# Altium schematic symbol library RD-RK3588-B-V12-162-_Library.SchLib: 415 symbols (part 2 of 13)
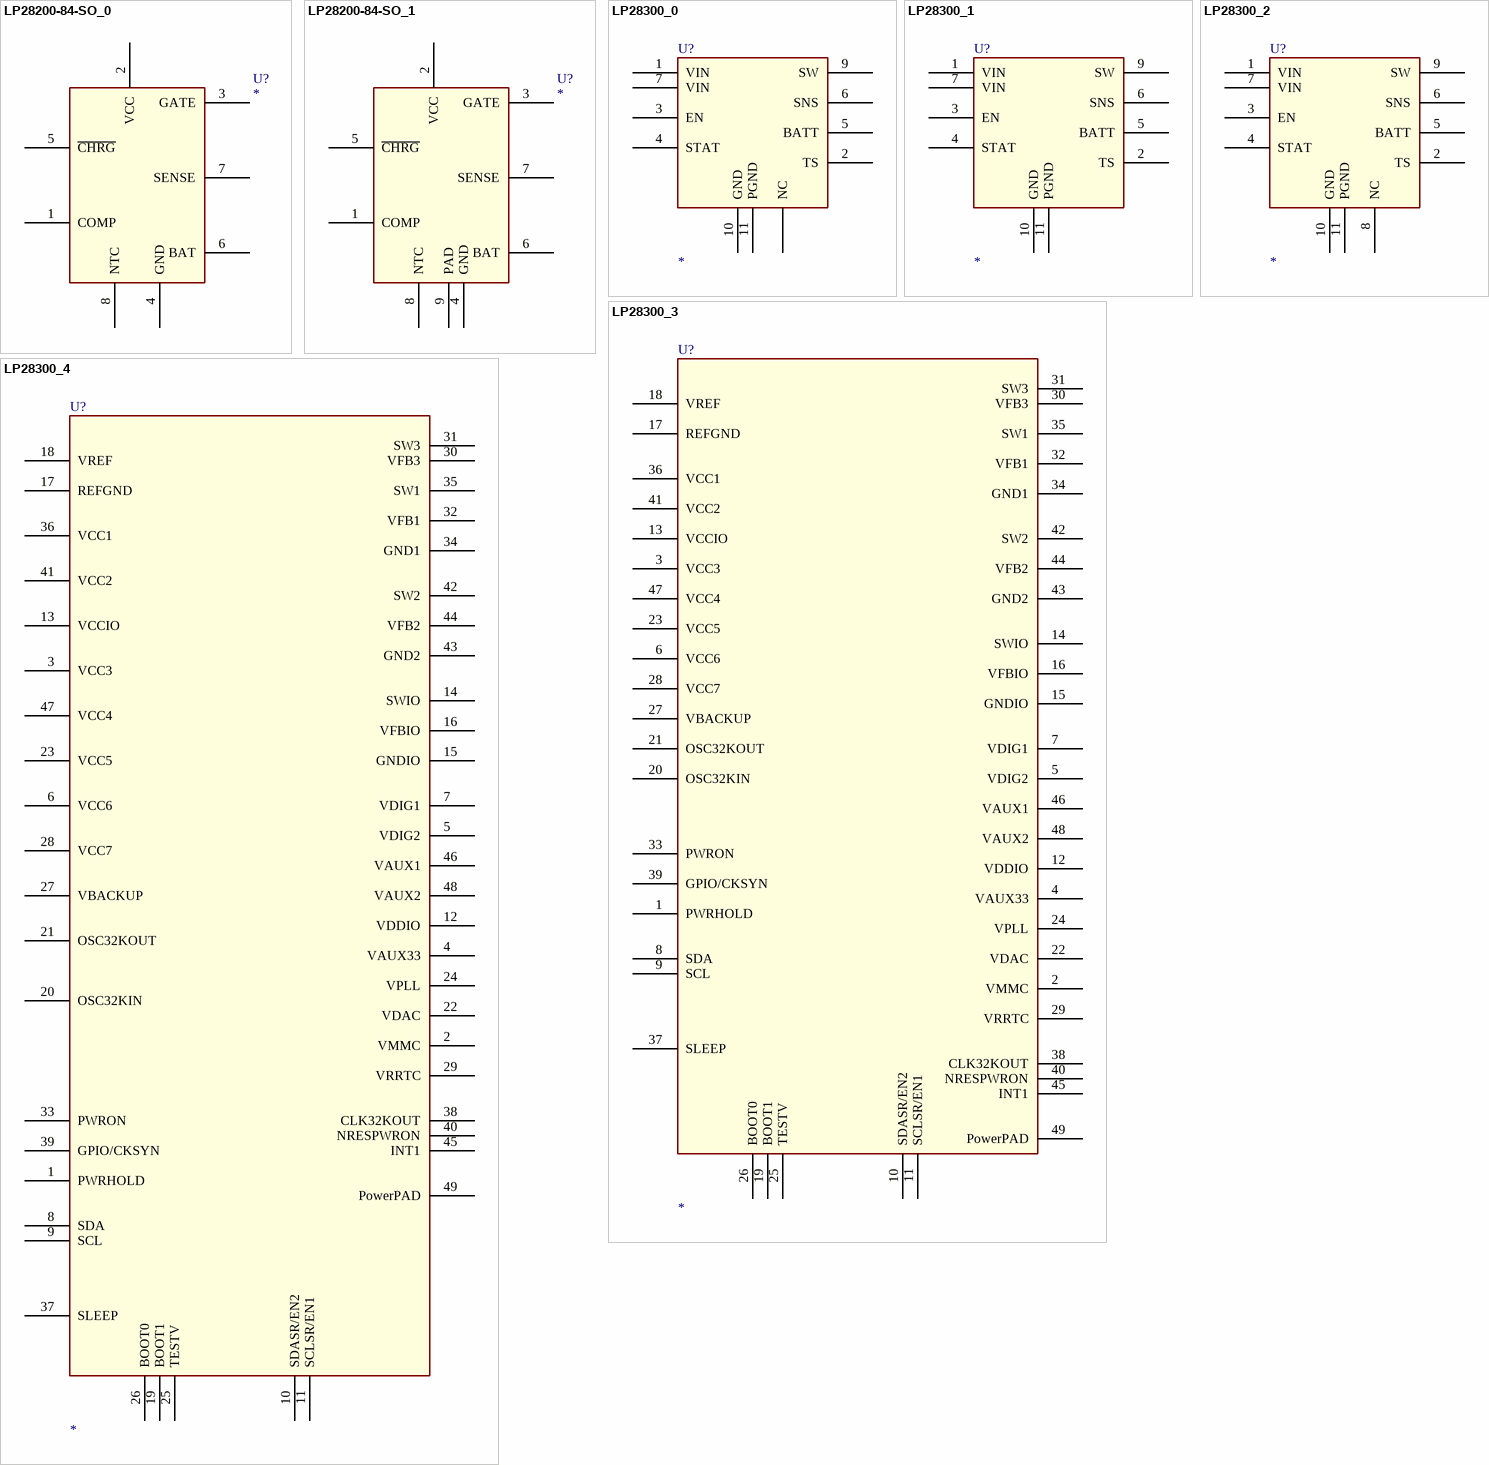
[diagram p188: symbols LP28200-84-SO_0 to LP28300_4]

## LP28300_3
designator U?
footprint TDFN10
pins: 1 PWRHOLD, 2 VMMC, 3 VCC3, 4 VAUX33, 5 VDIG2, 6 VCC6, 7 VDIG1, 8 SDA, 9 SCL, 10 SDASR/EN2, 11 SCLSR/EN1, 12 VDDIO, 13 VCCIO, 14 SWIO, 15 GNDIO, 16 VFBIO, 17 REFGND, 18 VREF, 19 BOOT1, 20 OSC32KIN, 21 OSC32KOUT, 22 VDAC, 23 VCC5, 24 VPLL, 25 TESTV, 26 BOOT0, 27 VBACKUP, 28 VCC7, 29 VRRTC, 30 VFB3, 31 SW3, 32 VFB1, 33 PWRON, 34 GND1, 35 SW1, 36 VCC1, 37 SLEEP, 38 CLK32KOUT, 39 GPIO/CKSYN, 40 NRESPWRON, 41 VCC2, 42 SW2, 43 GND2, 44 VFB2, 45 INT1, 46 VAUX1, 47 VCC4, 48 VAUX2, 49 PowerPAD

## LP28300_4
designator U?
footprint TDFN10
pins: 1 PWRHOLD, 2 VMMC, 3 VCC3, 4 VAUX33, 5 VDIG2, 6 VCC6, 7 VDIG1, 8 SDA, 9 SCL, 10 SDASR/EN2, 11 SCLSR/EN1, 12 VDDIO, 13 VCCIO, 14 SWIO, 15 GNDIO, 16 VFBIO, 17 REFGND, 18 VREF, 19 BOOT1, 20 OSC32KIN, 21 OSC32KOUT, 22 VDAC, 23 VCC5, 24 VPLL, 25 TESTV, 26 BOOT0, 27 VBACKUP, 28 VCC7, 29 VRRTC, 30 VFB3, 31 SW3, 32 VFB1, 33 PWRON, 34 GND1, 35 SW1, 36 VCC1, 37 SLEEP, 38 CLK32KOUT, 39 GPIO/CKSYN, 40 NRESPWRON, 41 VCC2, 42 SW2, 43 GND2, 44 VFB2, 45 INT1, 46 VAUX1, 47 VCC4, 48 VAUX2, 49 PowerPAD

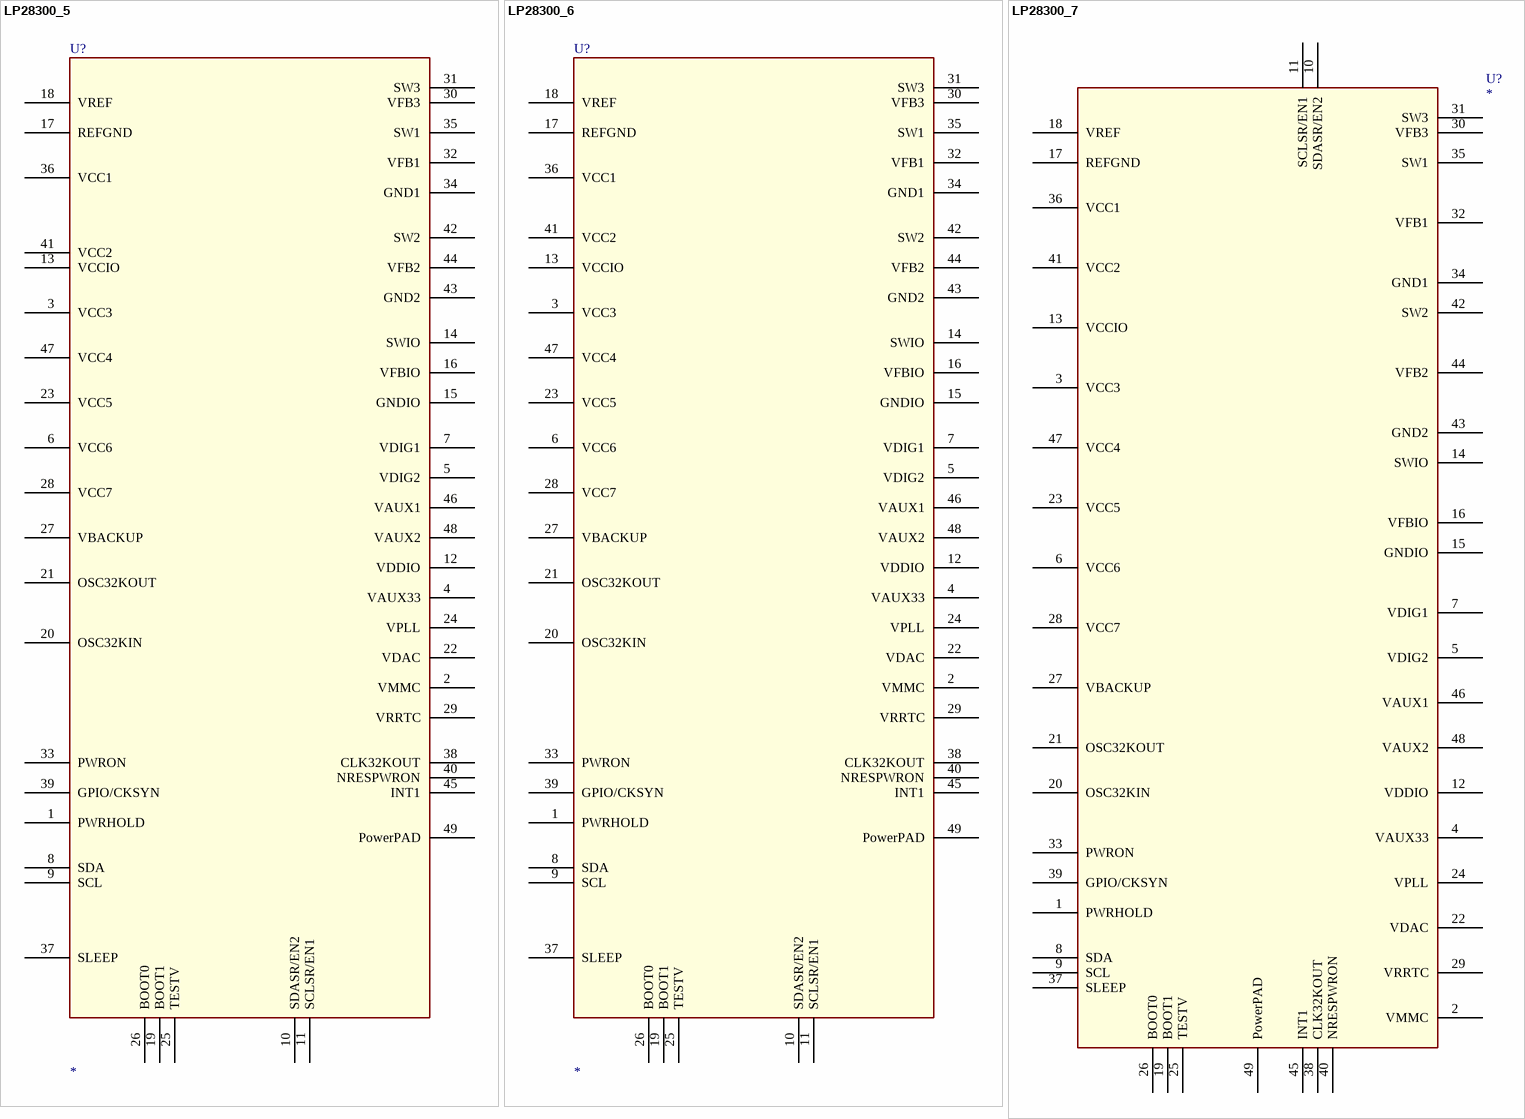
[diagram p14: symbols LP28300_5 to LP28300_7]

## LP28300_5
designator U?
footprint TDFN10
pins: 1 PWRHOLD, 2 VMMC, 3 VCC3, 4 VAUX33, 5 VDIG2, 6 VCC6, 7 VDIG1, 8 SDA, 9 SCL, 10 SDASR/EN2, 11 SCLSR/EN1, 12 VDDIO, 13 VCCIO, 14 SWIO, 15 GNDIO, 16 VFBIO, 17 REFGND, 18 VREF, 19 BOOT1, 20 OSC32KIN, 21 OSC32KOUT, 22 VDAC, 23 VCC5, 24 VPLL, 25 TESTV, 26 BOOT0, 27 VBACKUP, 28 VCC7, 29 VRRTC, 30 VFB3, 31 SW3, 32 VFB1, 33 PWRON, 34 GND1, 35 SW1, 36 VCC1, 37 SLEEP, 38 CLK32KOUT, 39 GPIO/CKSYN, 40 NRESPWRON, 41 VCC2, 42 SW2, 43 GND2, 44 VFB2, 45 INT1, 46 VAUX1, 47 VCC4, 48 VAUX2, 49 PowerPAD

## LP28300_6
designator U?
footprint TDFN10
pins: 1 PWRHOLD, 2 VMMC, 3 VCC3, 4 VAUX33, 5 VDIG2, 6 VCC6, 7 VDIG1, 8 SDA, 9 SCL, 10 SDASR/EN2, 11 SCLSR/EN1, 12 VDDIO, 13 VCCIO, 14 SWIO, 15 GNDIO, 16 VFBIO, 17 REFGND, 18 VREF, 19 BOOT1, 20 OSC32KIN, 21 OSC32KOUT, 22 VDAC, 23 VCC5, 24 VPLL, 25 TESTV, 26 BOOT0, 27 VBACKUP, 28 VCC7, 29 VRRTC, 30 VFB3, 31 SW3, 32 VFB1, 33 PWRON, 34 GND1, 35 SW1, 36 VCC1, 37 SLEEP, 38 CLK32KOUT, 39 GPIO/CKSYN, 40 NRESPWRON, 41 VCC2, 42 SW2, 43 GND2, 44 VFB2, 45 INT1, 46 VAUX1, 47 VCC4, 48 VAUX2, 49 PowerPAD

## LP28300_7
designator U?
footprint TDFN10
pins: 1 PWRHOLD, 2 VMMC, 3 VCC3, 4 VAUX33, 5 VDIG2, 6 VCC6, 7 VDIG1, 8 SDA, 9 SCL, 10 SDASR/EN2, 11 SCLSR/EN1, 12 VDDIO, 13 VCCIO, 14 SWIO, 15 GNDIO, 16 VFBIO, 17 REFGND, 18 VREF, 19 BOOT1, 20 OSC32KIN, 21 OSC32KOUT, 22 VDAC, 23 VCC5, 24 VPLL, 25 TESTV, 26 BOOT0, 27 VBACKUP, 28 VCC7, 29 VRRTC, 30 VFB3, 31 SW3, 32 VFB1, 33 PWRON, 34 GND1, 35 SW1, 36 VCC1, 37 SLEEP, 38 CLK32KOUT, 39 GPIO/CKSYN, 40 NRESPWRON, 41 VCC2, 42 SW2, 43 GND2, 44 VFB2, 45 INT1, 46 VAUX1, 47 VCC4, 48 VAUX2, 49 PowerPAD

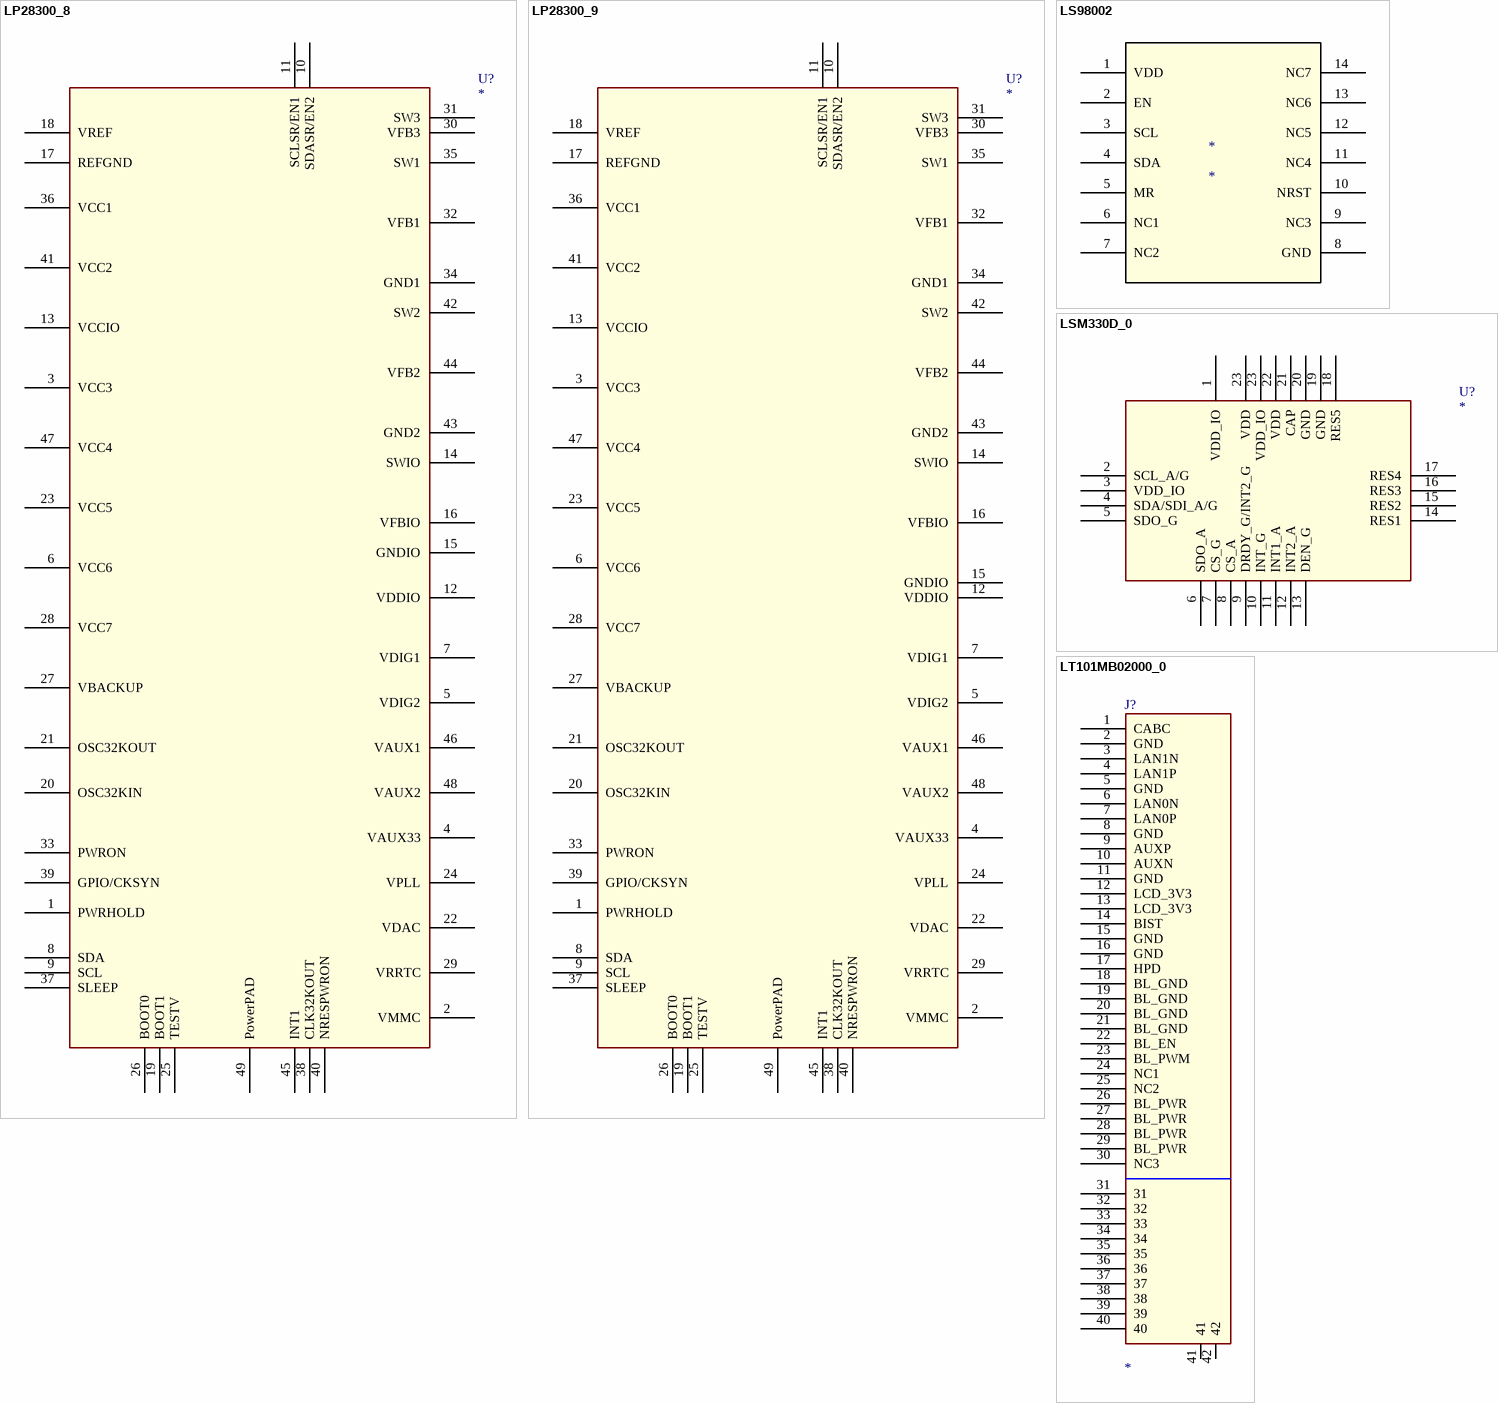
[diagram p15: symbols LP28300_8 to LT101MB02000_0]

## LP28300_8
designator U?
footprint TDFN10
pins: 1 PWRHOLD, 2 VMMC, 3 VCC3, 4 VAUX33, 5 VDIG2, 6 VCC6, 7 VDIG1, 8 SDA, 9 SCL, 10 SDASR/EN2, 11 SCLSR/EN1, 12 VDDIO, 13 VCCIO, 14 SWIO, 15 GNDIO, 16 VFBIO, 17 REFGND, 18 VREF, 19 BOOT1, 20 OSC32KIN, 21 OSC32KOUT, 22 VDAC, 23 VCC5, 24 VPLL, 25 TESTV, 26 BOOT0, 27 VBACKUP, 28 VCC7, 29 VRRTC, 30 VFB3, 31 SW3, 32 VFB1, 33 PWRON, 34 GND1, 35 SW1, 36 VCC1, 37 SLEEP, 38 CLK32KOUT, 39 GPIO/CKSYN, 40 NRESPWRON, 41 VCC2, 42 SW2, 43 GND2, 44 VFB2, 45 INT1, 46 VAUX1, 47 VCC4, 48 VAUX2, 49 PowerPAD

## LP28300_9
designator U?
footprint TDFN10
pins: 1 PWRHOLD, 2 VMMC, 3 VCC3, 4 VAUX33, 5 VDIG2, 6 VCC6, 7 VDIG1, 8 SDA, 9 SCL, 10 SDASR/EN2, 11 SCLSR/EN1, 12 VDDIO, 13 VCCIO, 14 SWIO, 15 GNDIO, 16 VFBIO, 17 REFGND, 18 VREF, 19 BOOT1, 20 OSC32KIN, 21 OSC32KOUT, 22 VDAC, 23 VCC5, 24 VPLL, 25 TESTV, 26 BOOT0, 27 VBACKUP, 28 VCC7, 29 VRRTC, 30 VFB3, 31 SW3, 32 VFB1, 33 PWRON, 34 GND1, 35 SW1, 36 VCC1, 37 SLEEP, 38 CLK32KOUT, 39 GPIO/CKSYN, 40 NRESPWRON, 41 VCC2, 42 SW2, 43 GND2, 44 VFB2, 45 INT1, 46 VAUX1, 47 VCC4, 48 VAUX2, 49 PowerPAD

## LS98002
designator *
pins: 1 VDD, 2 EN, 3 SCL, 4 SDA, 5 MR, 6 NC1, 7 NC2, 8 GND, 9 NC3, 10 NRST, 11 NC4, 12 NC5, 13 NC6, 14 NC7

## LSM330D_0
designator U?
footprint L3G4200D
pins: 1 VDD_IO, 2 SCL_A/G, 3 VDD_IO, 4 SDA/SDI_A/G, 5 SDO_G, 6 SDO_A, 7 CS_G, 8 CS_A, 9 DRDY_G/INT2_G, 10 INT_G, 11 INT1_A, 12 INT2_A, 13 DEN_G, 14 RES1, 15 RES2, 16 RES3, 17 RES4, 18 RES5, 19 GND (power), 20 GND (power), 21 CAP, 22 VDD, 23 VDD, 23 VDD_IO

## LT101MB02000_0
designator J?
pins: 1 CABC, 2 GND (power), 3 LAN1N, 4 LAN1P, 5 GND (power), 6 LAN0N, 7 LAN0P, 8 GND (power), 9 AUXP, 10 AUXN, 11 GND (power), 12 LCD_3V3 (power), 13 LCD_3V3 (power), 14 BIST, 15 GND (power), 16 GND (power), 17 HPD, 18 BL_GND (power), 19 BL_GND (power), 20 BL_GND (power), 21 BL_GND (power), 22 BL_EN, 23 BL_PWM, 24 NC1, 25 NC2, 26 BL_PWR (power), 27 BL_PWR (power), 28 BL_PWR (power), 29 BL_PWR (power), 30 NC3, 31, 32, 33, 34, 35, 36, 37, 38, 39, 40, 41, 42

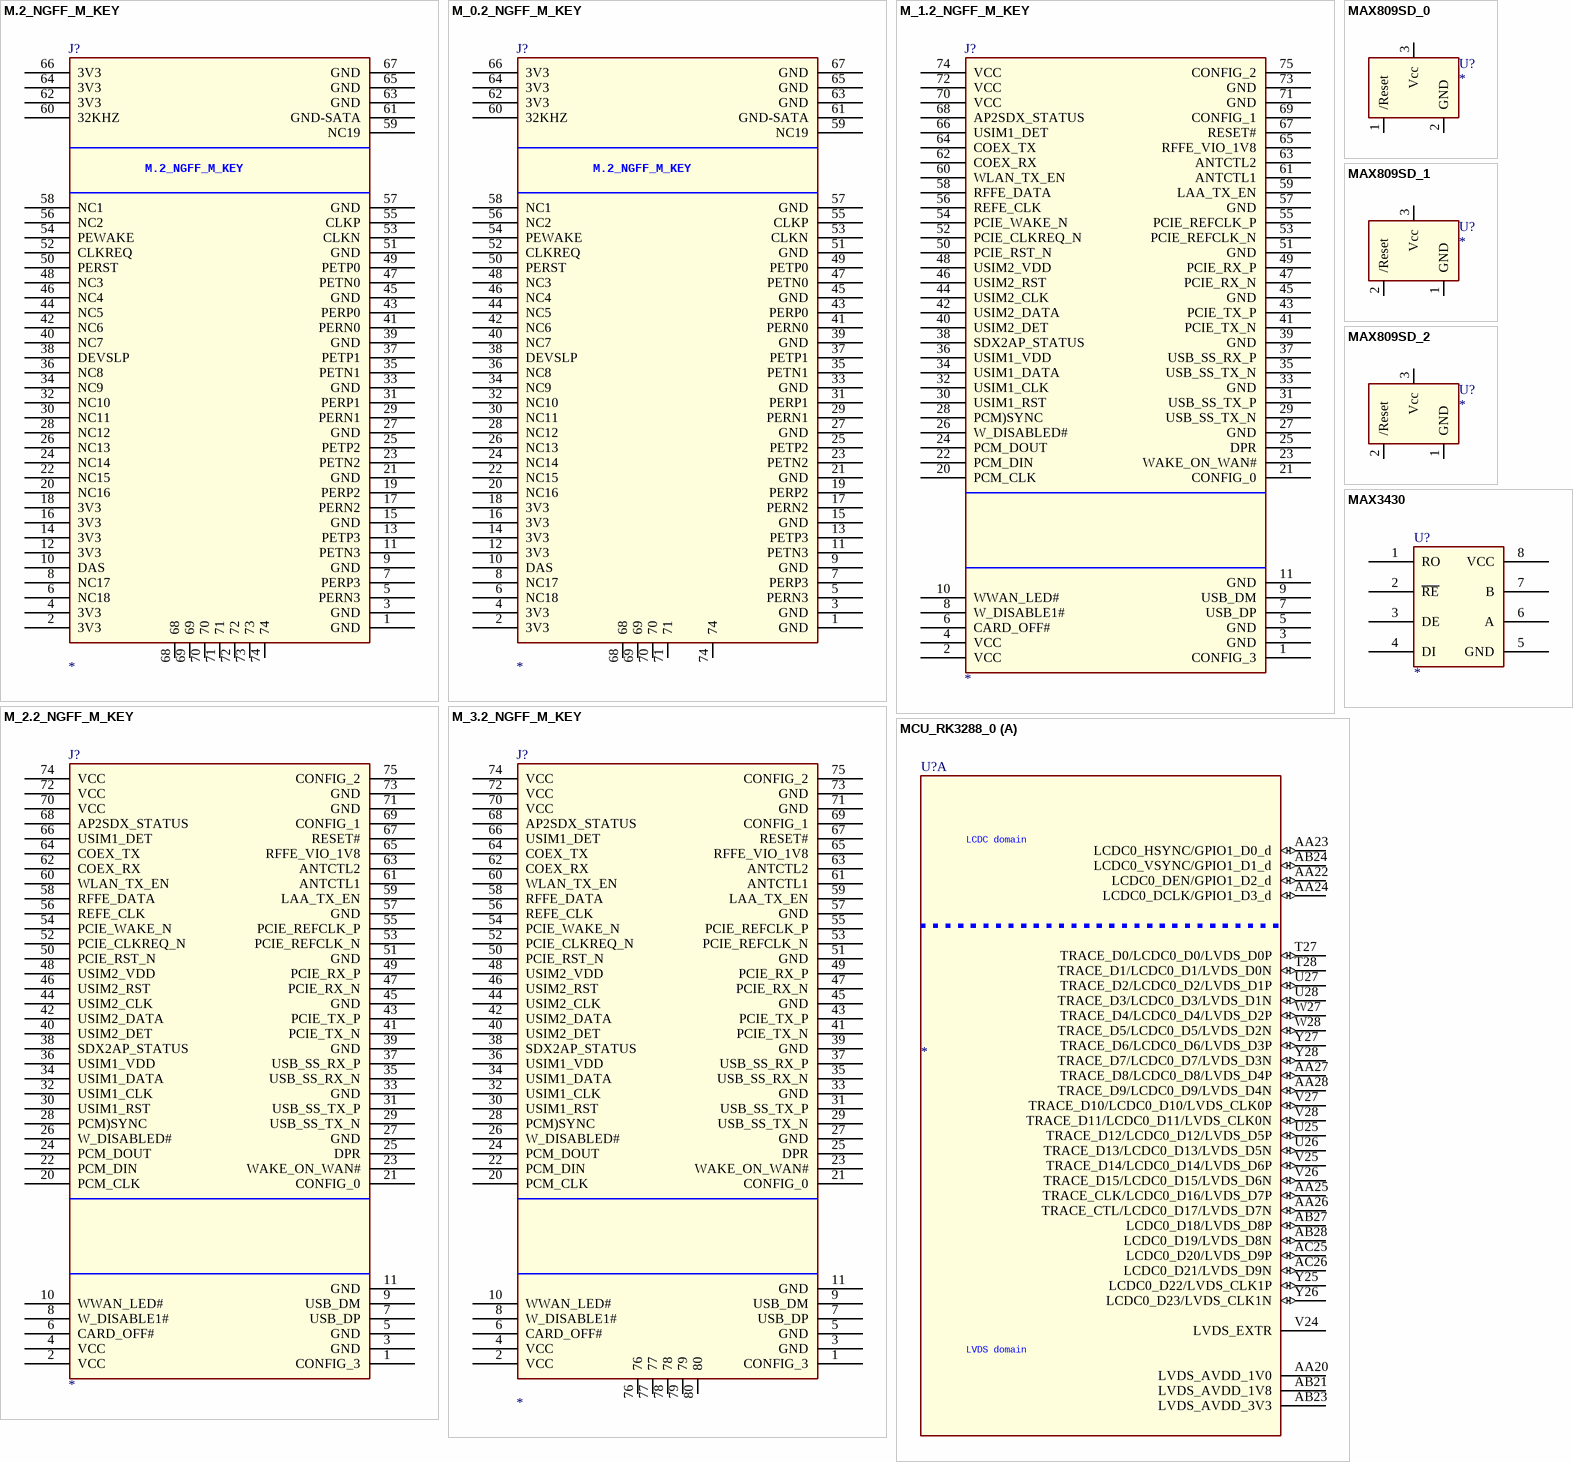
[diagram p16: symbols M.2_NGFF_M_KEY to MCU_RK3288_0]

## M.2_NGFF_M_KEY
designator J?
pins: 1 GND (power), 2 3V3 (power), 3 GND (power), 4 3V3 (power), 5 PERN3, 6 NC18, 7 PERP3, 8 NC17, 9 GND (power), 10 DAS, 11 PETN3, 12 3V3 (power), 13 PETP3, 14 3V3 (power), 15 GND (power), 16 3V3 (power), 17 PERN2, 18 3V3 (power), 19 PERP2, 20 NC16, 21 GND (power), 22 NC15, 23 PETN2, 24 NC14, 25 PETP2, 26 NC13, 27 GND (power), 28 NC12, 29 PERN1, 30 NC11, 31 PERP1, 32 NC10, 33 GND (power), 34 NC9, 35 PETN1, 36 NC8, 37 PETP1, 38 DEVSLP, 39 GND (power), 40 NC7, 41 PERN0, 42 NC6, 43 PERP0, 44 NC5, 45 GND (power), 46 NC4, 47 PETN0, 48 NC3, 49 PETP0, 50 PERST, 51 GND (power), 52 CLKREQ, 53 CLKN, 54 PEWAKE, 55 CLKP, 56 NC2, 57 GND (power), 58 NC1, 59 NC19, 60 32KHZ, 61 GND-SATA, 62 3V3 (power), 63 GND (power), 64 3V3 (power), 65 GND (power), 66 3V3 (power), 67 GND (power), 68, 69, 70, 71, 72, 73, 74

## M_0.2_NGFF_M_KEY
designator J?
pins: 1 GND (power), 2 3V3 (power), 3 GND (power), 4 3V3 (power), 5 PERN3, 6 NC18, 7 PERP3, 8 NC17, 9 GND (power), 10 DAS, 11 PETN3, 12 3V3 (power), 13 PETP3, 14 3V3 (power), 15 GND (power), 16 3V3 (power), 17 PERN2, 18 3V3 (power), 19 PERP2, 20 NC16, 21 GND (power), 22 NC15, 23 PETN2, 24 NC14, 25 PETP2, 26 NC13, 27 GND (power), 28 NC12, 29 PERN1, 30 NC11, 31 PERP1, 32 NC10, 33 GND (power), 34 NC9, 35 PETN1, 36 NC8, 37 PETP1, 38 DEVSLP, 39 GND (power), 40 NC7, 41 PERN0, 42 NC6, 43 PERP0, 44 NC5, 45 GND (power), 46 NC4, 47 PETN0, 48 NC3, 49 PETP0, 50 PERST, 51 GND (power), 52 CLKREQ, 53 CLKN, 54 PEWAKE, 55 CLKP, 56 NC2, 57 GND (power), 58 NC1, 59 NC19, 60 32KHZ, 61 GND-SATA, 62 3V3 (power), 63 GND (power), 64 3V3 (power), 65 GND (power), 66 3V3 (power), 67 GND (power), 68, 69, 70, 71, 74

## M_1.2_NGFF_M_KEY
designator J?
pins: 1 CONFIG_3, 2 VCC, 3 GND, 4 VCC, 5 GND, 6 CARD_OFF#, 7 USB_DP, 8 W_DISABLE1#, 9 USB_DM, 10 WWAN_LED#, 11 GND, 20 PCM_CLK, 21 CONFIG_0, 22 PCM_DIN, 23 WAKE_ON_WAN#, 24 PCM_DOUT, 25 DPR, 26 W_DISABLED#, 27 GND, 28 PCM)SYNC, 29 USB_SS_TX_N, 30 USIM1_RST, 31 USB_SS_TX_P, 32 USIM1_CLK, 33 GND, 34 USIM1_DATA, 35 USB_SS_TX_N, 36 USIM1_VDD, 37 USB_SS_RX_P, 38 SDX2AP_STATUS, 39 GND, 40 USIM2_DET, 41 PCIE_TX_N, 42 USIM2_DATA, 43 PCIE_TX_P, 44 USIM2_CLK, 45 GND, 46 USIM2_RST, 47 PCIE_RX_N, 48 USIM2_VDD, 49 PCIE_RX_P, 50 PCIE_RST_N, 51 GND, 52 PCIE_CLKREQ_N, 53 PCIE_REFCLK_N, 54 PCIE_WAKE_N, 55 PCIE_REFCLK_P, 56 REFE_CLK, 57 GND, 58 RFFE_DATA, 59 LAA_TX_EN, 60 WLAN_TX_EN, 61 ANTCTL1, 62 COEX_RX, 63 ANTCTL2, 64 COEX_TX, 65 RFFE_VIO_1V8, 66 USIM1_DET, 67 RESET#, 68 AP2SDX_STATUS, 69 CONFIG_1, 70 VCC, 71 GND, 72 VCC, 73 GND, 74 VCC, 75 CONFIG_2

## M_2.2_NGFF_M_KEY
designator J?
pins: 1 CONFIG_3, 2 VCC (power), 3 GND (power), 4 VCC (power), 5 GND (power), 6 CARD_OFF#, 7 USB_DP, 8 W_DISABLE1#, 9 USB_DM, 10 WWAN_LED#, 11 GND (power), 20 PCM_CLK, 21 CONFIG_0, 22 PCM_DIN, 23 WAKE_ON_WAN#, 24 PCM_DOUT, 25 DPR, 26 W_DISABLED#, 27 GND (power), 28 PCM)SYNC, 29 USB_SS_TX_N, 30 USIM1_RST, 31 USB_SS_TX_P, 32 USIM1_CLK, 33 GND (power), 34 USIM1_DATA, 35 USB_SS_RX_N, 36 USIM1_VDD, 37 USB_SS_RX_P, 38 SDX2AP_STATUS, 39 GND (power), 40 USIM2_DET, 41 PCIE_TX_N, 42 USIM2_DATA, 43 PCIE_TX_P, 44 USIM2_CLK, 45 GND (power), 46 USIM2_RST, 47 PCIE_RX_N, 48 USIM2_VDD, 49 PCIE_RX_P, 50 PCIE_RST_N, 51 GND (power), 52 PCIE_CLKREQ_N, 53 PCIE_REFCLK_N, 54 PCIE_WAKE_N, 55 PCIE_REFCLK_P, 56 REFE_CLK, 57 GND (power), 58 RFFE_DATA, 59 LAA_TX_EN, 60 WLAN_TX_EN, 61 ANTCTL1, 62 COEX_RX, 63 ANTCTL2, 64 COEX_TX, 65 RFFE_VIO_1V8, 66 USIM1_DET, 67 RESET#, 68 AP2SDX_STATUS, 69 CONFIG_1, 70 VCC (power), 71 GND (power), 72 VCC (power), 73 GND (power), 74 VCC (power), 75 CONFIG_2

## M_3.2_NGFF_M_KEY
designator J?
pins: 1 CONFIG_3, 2 VCC (power), 3 GND (power), 4 VCC (power), 5 GND (power), 6 CARD_OFF#, 7 USB_DP, 8 W_DISABLE1#, 9 USB_DM, 10 WWAN_LED#, 11 GND (power), 20 PCM_CLK, 21 CONFIG_0, 22 PCM_DIN, 23 WAKE_ON_WAN#, 24 PCM_DOUT, 25 DPR, 26 W_DISABLED#, 27 GND (power), 28 PCM)SYNC, 29 USB_SS_TX_N, 30 USIM1_RST, 31 USB_SS_TX_P, 32 USIM1_CLK, 33 GND (power), 34 USIM1_DATA, 35 USB_SS_RX_N, 36 USIM1_VDD, 37 USB_SS_RX_P, 38 SDX2AP_STATUS, 39 GND (power), 40 USIM2_DET, 41 PCIE_TX_N, 42 USIM2_DATA, 43 PCIE_TX_P, 44 USIM2_CLK, 45 GND (power), 46 USIM2_RST, 47 PCIE_RX_N, 48 USIM2_VDD, 49 PCIE_RX_P, 50 PCIE_RST_N, 51 GND (power), 52 PCIE_CLKREQ_N, 53 PCIE_REFCLK_N, 54 PCIE_WAKE_N, 55 PCIE_REFCLK_P, 56 REFE_CLK, 57 GND (power), 58 RFFE_DATA, 59 LAA_TX_EN, 60 WLAN_TX_EN, 61 ANTCTL1, 62 COEX_RX, 63 ANTCTL2, 64 COEX_TX, 65 RFFE_VIO_1V8, 66 USIM1_DET, 67 RESET#, 68 AP2SDX_STATUS, 69 CONFIG_1, 70 VCC (power), 71 GND (power), 72 VCC (power), 73 GND (power), 74 VCC (power), 75 CONFIG_2, 76, 77, 78, 79, 80

## MAX809SD_0
designator U?
pins: 1 /Reset, 2 GND, 3 Vcc

## MAX809SD_1
designator U?
pins: 1 GND, 2 /Reset, 3 Vcc

## MAX809SD_2
designator U?
pins: 1 GND, 2 /Reset, 3 Vcc

## MAX3430
designator U?
pins: 1 RO, 2 ~{RE}, 3 DE, 4 DI, 5 GND, 6 A, 7 B, 8 VCC

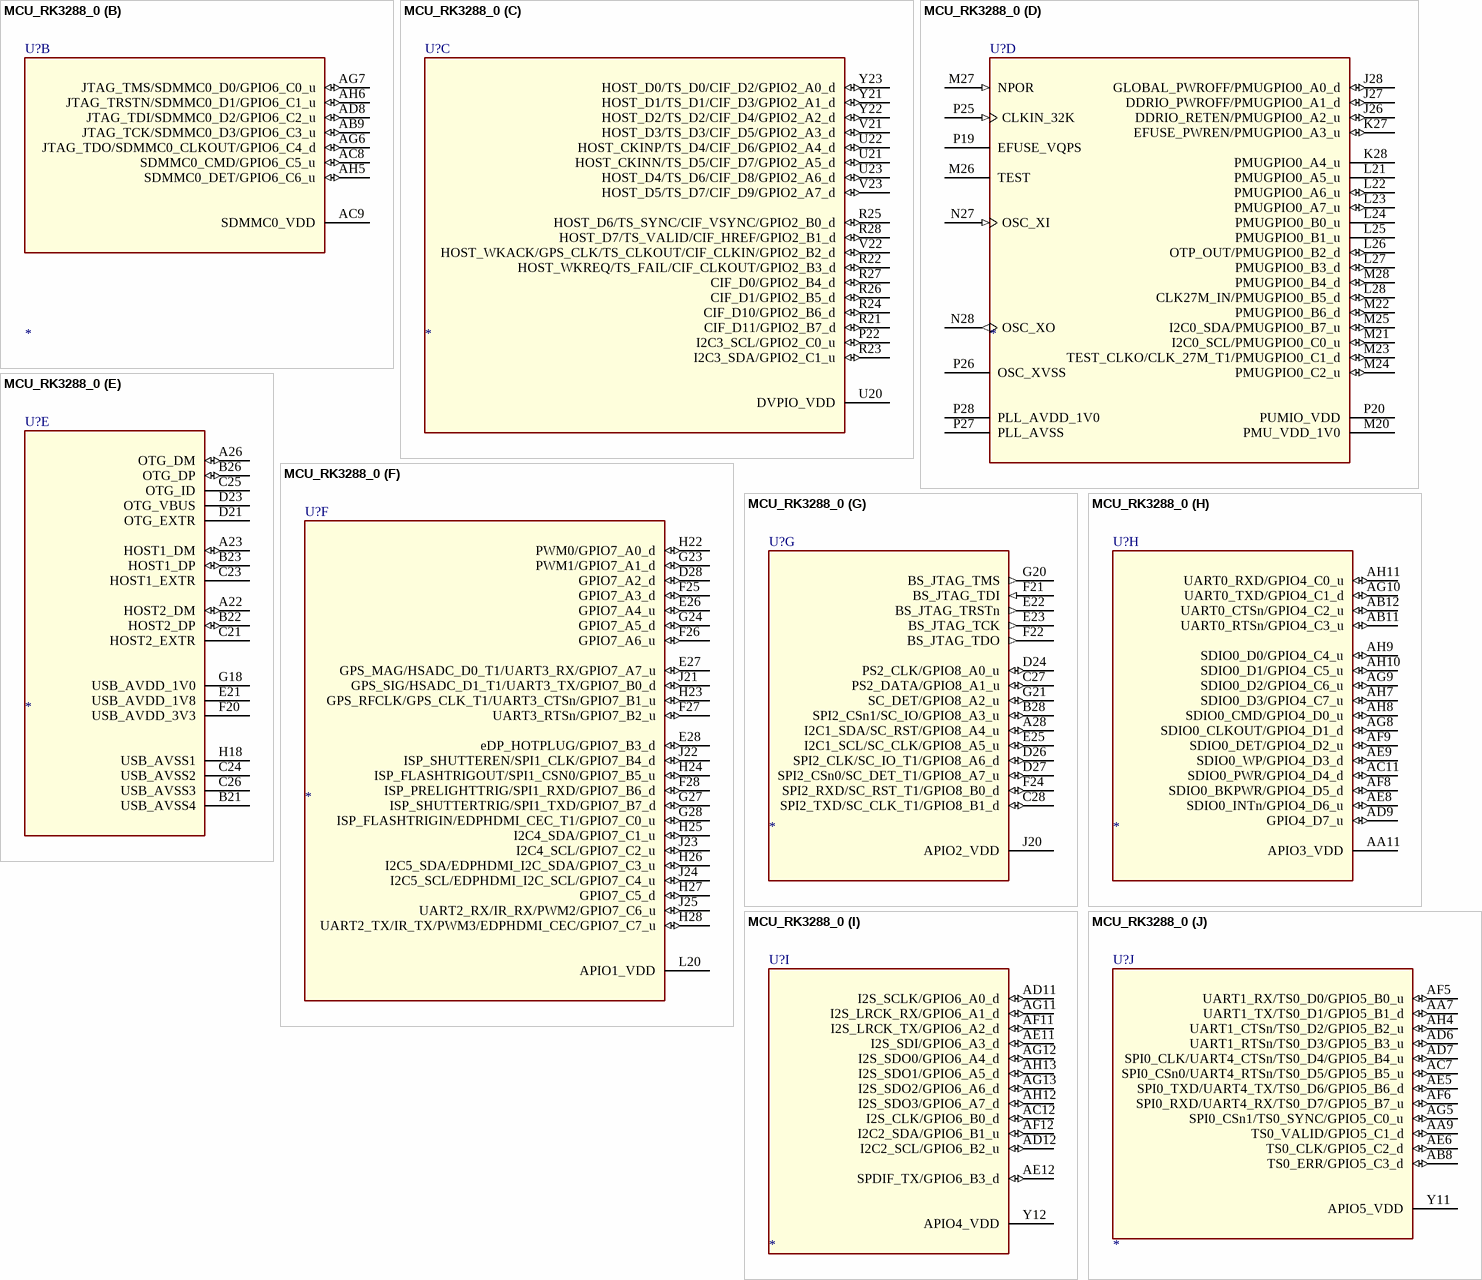
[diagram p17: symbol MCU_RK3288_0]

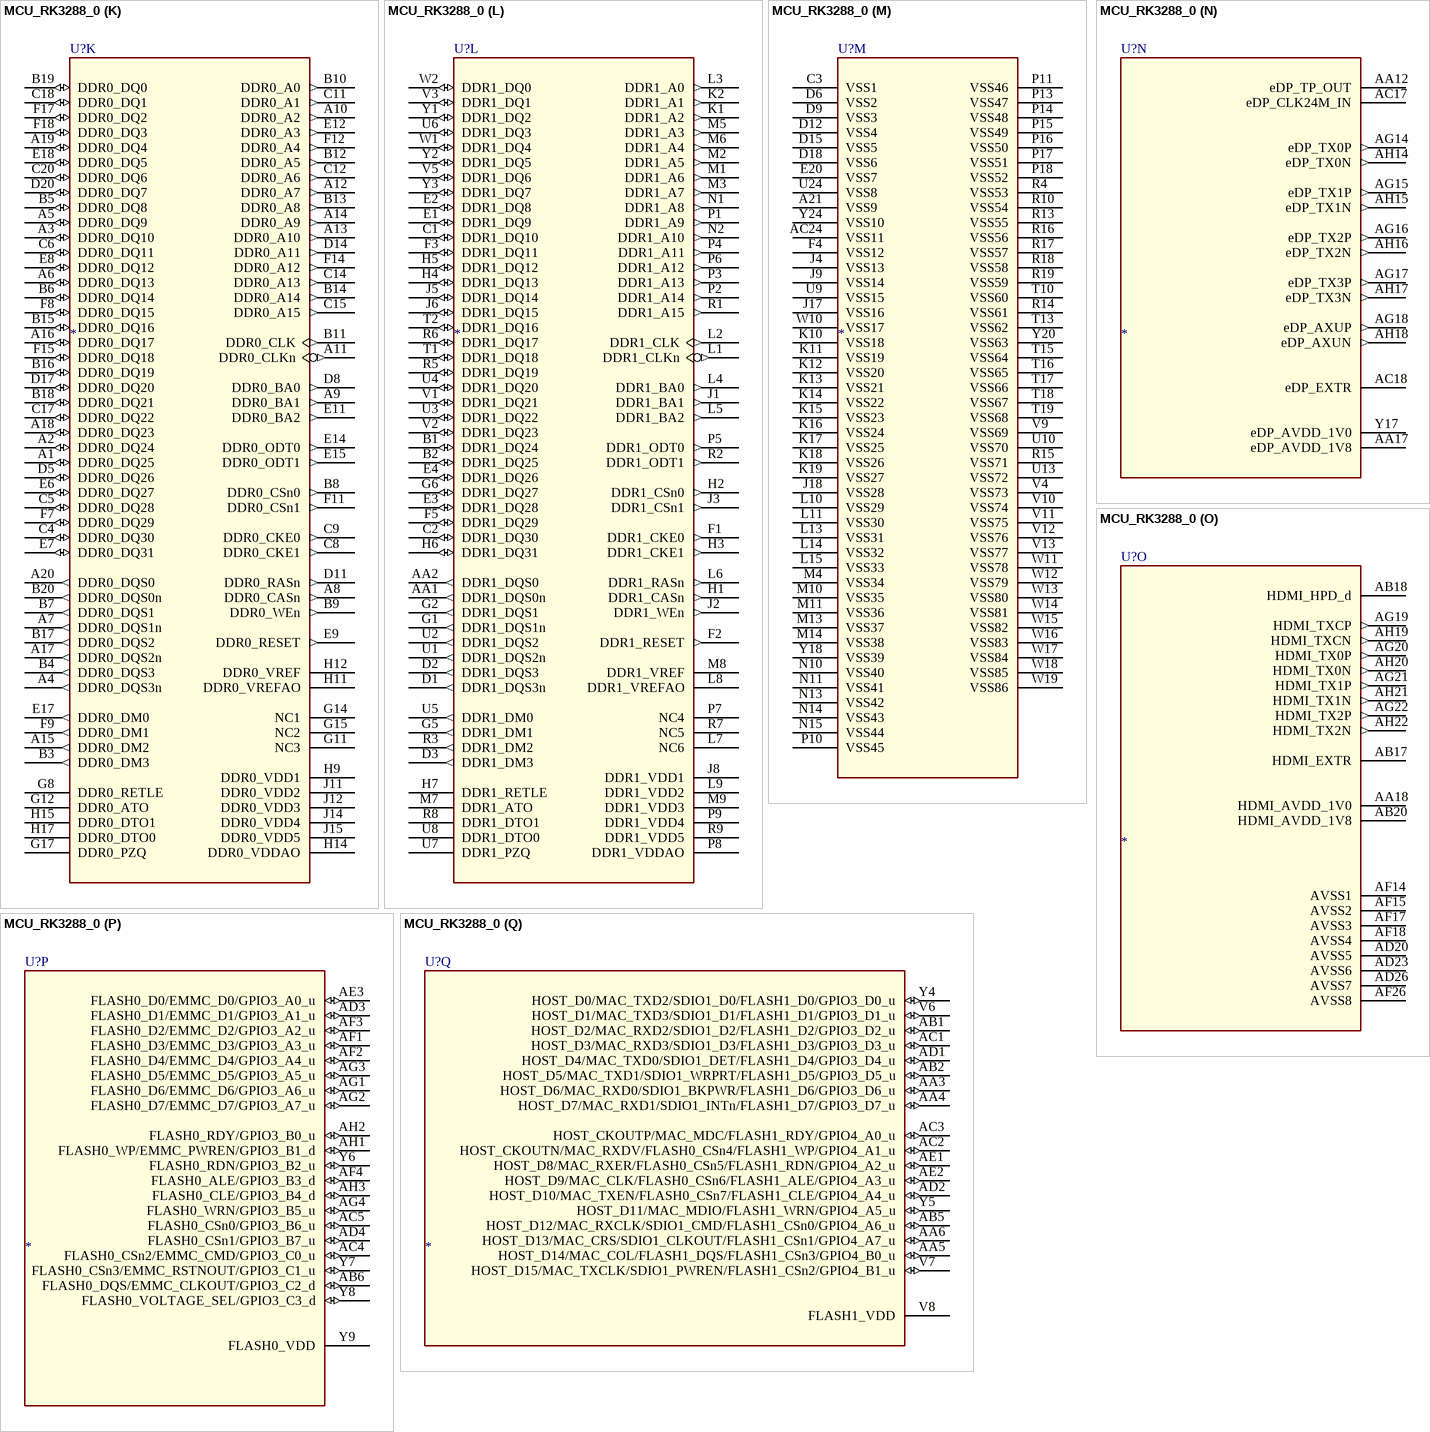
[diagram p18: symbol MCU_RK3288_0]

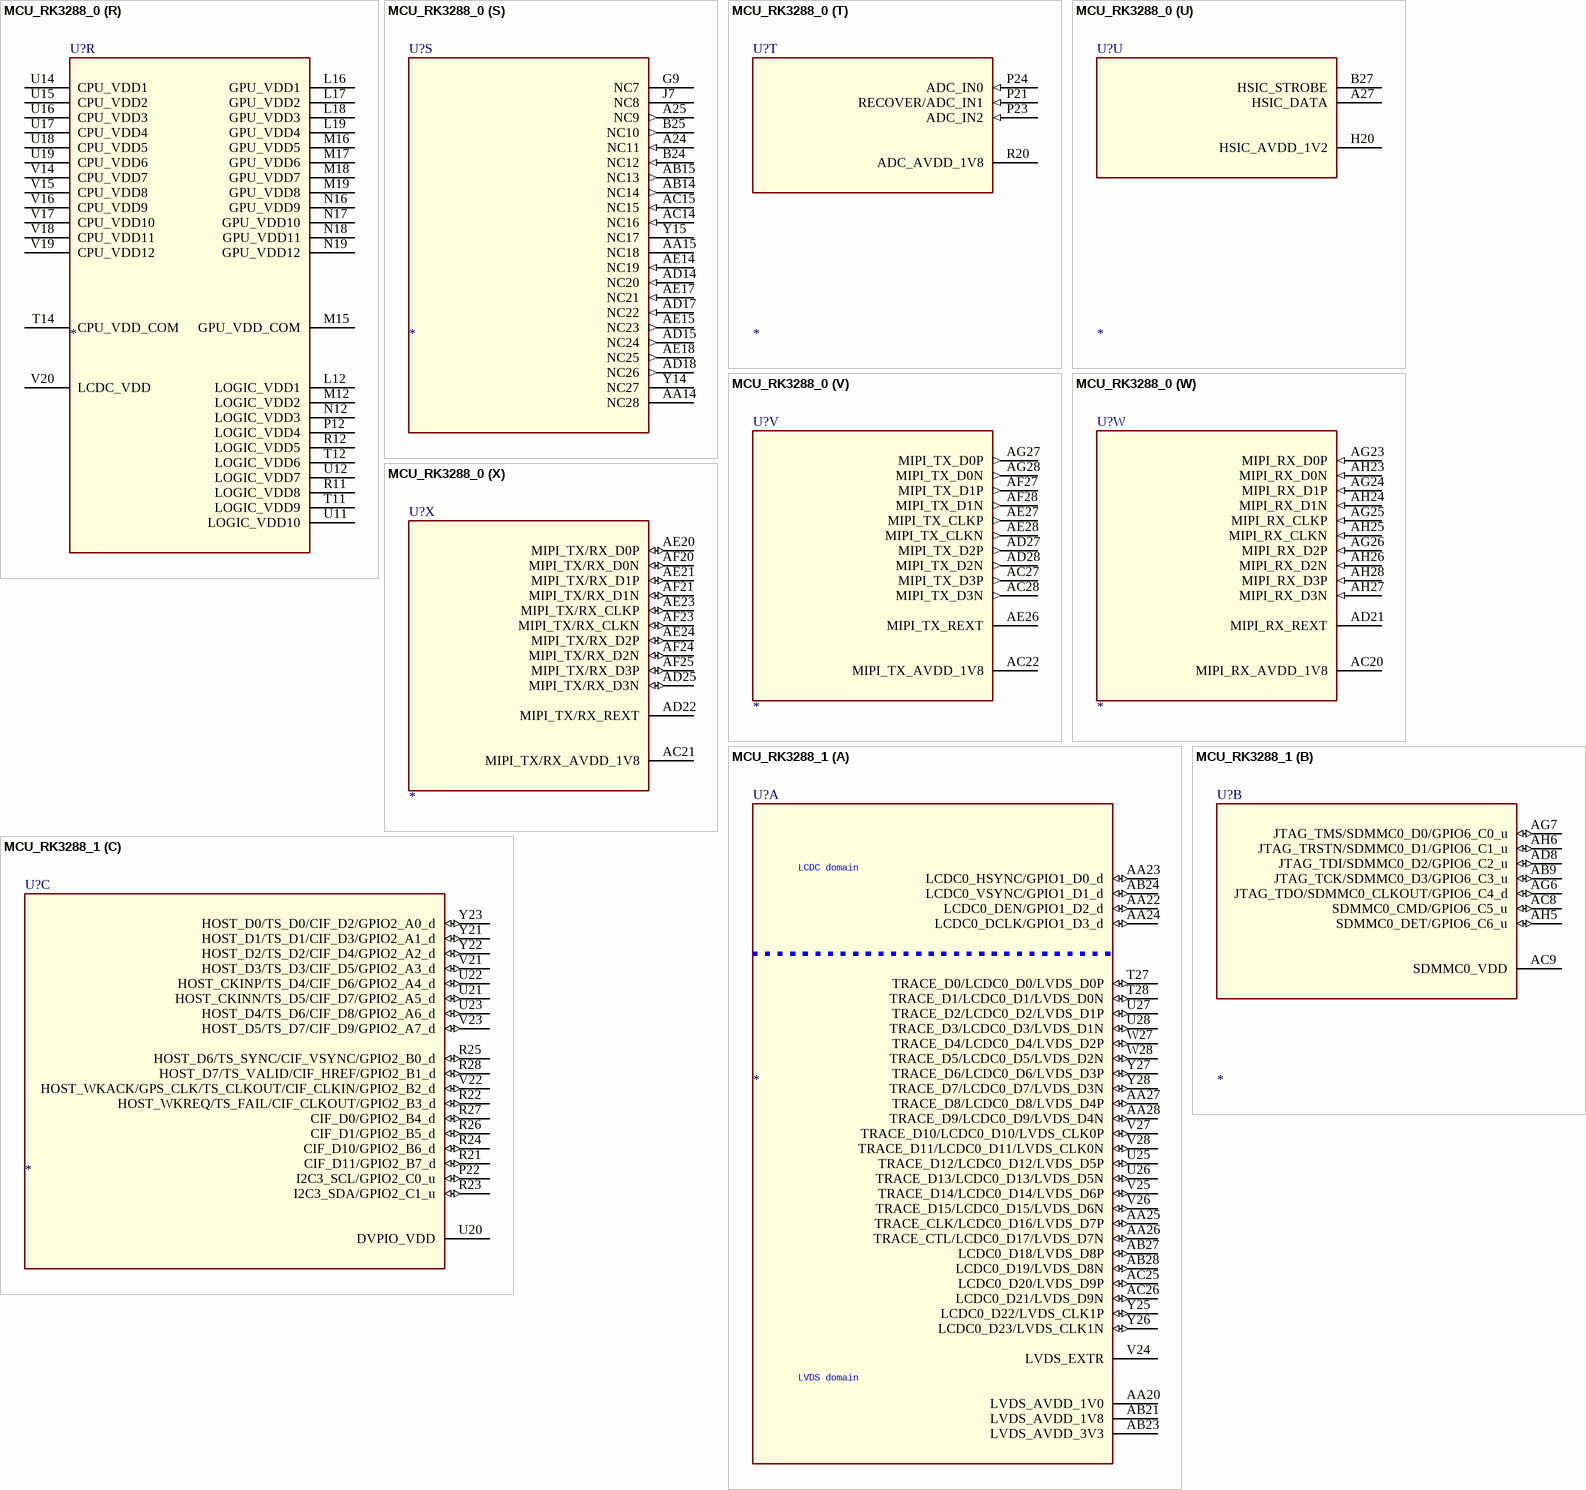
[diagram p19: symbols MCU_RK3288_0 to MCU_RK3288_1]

## MCU_RK3288_0
designator U?
footprint BGA453-19X19
part A pins: AA20 LVDS_AVDD_1V0 (power), AA22 LCDC0_DEN/GPIO1_D2_d (io), AA23 LCDC0_HSYNC/GPIO1_D0_d (io), AA24 LCDC0_DCLK/GPIO1_D3_d (io), AA25 TRACE_CLK/LCDC0_D16/LVDS_D7P (io), AA26 TRACE_CTL/LCDC0_D17/LVDS_D7N (io), AA27 TRACE_D8/LCDC0_D8/LVDS_D4P (io), AA28 TRACE_D9/LCDC0_D9/LVDS_D4N (io), AB21 LVDS_AVDD_1V8 (power), AB23 LVDS_AVDD_3V3 (power), AB24 LCDC0_VSYNC/GPIO1_D1_d (io), AB27 LCDC0_D18/LVDS_D8P (io), AB28 LCDC0_D19/LVDS_D8N (io), AC25 LCDC0_D20/LVDS_D9P (io), AC26 LCDC0_D21/LVDS_D9N (io), T27 TRACE_D0/LCDC0_D0/LVDS_D0P (io), T28 TRACE_D1/LCDC0_D1/LVDS_D0N (io), U25 TRACE_D12/LCDC0_D12/LVDS_D5P (io), U26 TRACE_D13/LCDC0_D13/LVDS_D5N (io), U27 TRACE_D2/LCDC0_D2/LVDS_D1P (io), U28 TRACE_D3/LCDC0_D3/LVDS_D1N (io), V24 LVDS_EXTR, V25 TRACE_D14/LCDC0_D14/LVDS_D6P (io), V26 TRACE_D15/LCDC0_D15/LVDS_D6N (io), V27 TRACE_D10/LCDC0_D10/LVDS_CLK0P (io), V28 TRACE_D11/LCDC0_D11/LVDS_CLK0N (io), W27 TRACE_D4/LCDC0_D4/LVDS_D2P (io), W28 TRACE_D5/LCDC0_D5/LVDS_D2N (io), Y25 LCDC0_D22/LVDS_CLK1P (io), Y26 LCDC0_D23/LVDS_CLK1N (io), Y27 TRACE_D6/LCDC0_D6/LVDS_D3P (io), Y28 TRACE_D7/LCDC0_D7/LVDS_D3N (io)
part B pins: AB9 JTAG_TCK/SDMMC0_D3/GPIO6_C3_u (io), AC8 SDMMC0_CMD/GPIO6_C5_u (io), AC9 SDMMC0_VDD (power), AD8 JTAG_TDI/SDMMC0_D2/GPIO6_C2_u (io), AG6 JTAG_TDO/SDMMC0_CLKOUT/GPIO6_C4_d (io), AG7 JTAG_TMS/SDMMC0_D0/GPIO6_C0_u (io), AH5 SDMMC0_DET/GPIO6_C6_u (io), AH6 JTAG_TRSTN/SDMMC0_D1/GPIO6_C1_u (io)
part C pins: P22 I2C3_SCL/GPIO2_C0_u (io), R21 CIF_D11/GPIO2_B7_d (io), R22 HOST_WKREQ/TS_FAIL/CIF_CLKOUT/GPIO2_B3_d (io), R23 I2C3_SDA/GPIO2_C1_u (io), R24 CIF_D10/GPIO2_B6_d (io), R25 HOST_D6/TS_SYNC/CIF_VSYNC/GPIO2_B0_d (io), R26 CIF_D1/GPIO2_B5_d (io), R27 CIF_D0/GPIO2_B4_d (io), R28 HOST_D7/TS_VALID/CIF_HREF/GPIO2_B1_d (io), U20 DVPIO_VDD (power), U21 HOST_CKINN/TS_D5/CIF_D7/GPIO2_A5_d (io), U22 HOST_CKINP/TS_D4/CIF_D6/GPIO2_A4_d (io), U23 HOST_D4/TS_D6/CIF_D8/GPIO2_A6_d (io), V21 HOST_D3/TS_D3/CIF_D5/GPIO2_A3_d (io), V22 HOST_WKACK/GPS_CLK/TS_CLKOUT/CIF_CLKIN/GPIO2_B2_d (io), V23 HOST_D5/TS_D7/CIF_D9/GPIO2_A7_d (io), Y21 HOST_D1/TS_D1/CIF_D3/GPIO2_A1_d (io), Y22 HOST_D2/TS_D2/CIF_D4/GPIO2_A2_d (io), Y23 HOST_D0/TS_D0/CIF_D2/GPIO2_A0_d (io)
part D pins: J26 DDRIO_RETEN/PMUGPIO0_A2_u (io), J27 DDRIO_PWROFF/PMUGPIO0_A1_d (io), J28 GLOBAL_PWROFF/PMUGPIO0_A0_d (io), K27 EFUSE_PWREN/PMUGPIO0_A3_u (io), K28 PMUGPIO0_A4_u, L21 PMUGPIO0_A5_u, L22 PMUGPIO0_A6_u (io), L23 PMUGPIO0_A7_u (io), L24 PMUGPIO0_B0_u, L25 PMUGPIO0_B1_u, L26 OTP_OUT/PMUGPIO0_B2_d (io), L27 PMUGPIO0_B3_d (io), L28 CLK27M_IN/PMUGPIO0_B5_d (io), M20 PMU_VDD_1V0 (power), M21 I2C0_SCL/PMUGPIO0_C0_u (io), M22 PMUGPIO0_B6_d (io), M23 TEST_CLKO/CLK_27M_T1/PMUGPIO0_C1_d (io), M24 PMUGPIO0_C2_u (io), M25 I2C0_SDA/PMUGPIO0_B7_u (io), M26 TEST, M27 NPOR (in), M28 PMUGPIO0_B4_d (io), N27 OSC_XI (in), N28 OSC_XO (out), P19 EFUSE_VQPS (power), P20 PUMIO_VDD (power), P25 CLKIN_32K (in), P26 OSC_XVSS (power), P27 PLL_AVSS (power), P28 PLL_AVDD_1V0 (power)
part E pins: A22 HOST2_DM (io), A23 HOST1_DM (io), A26 OTG_DM (io), B21 USB_AVSS4 (power), B22 HOST2_DP (io), B23 HOST1_DP (io), B26 OTG_DP (io), C21 HOST2_EXTR, C23 HOST1_EXTR, C24 USB_AVSS2 (power), C25 OTG_ID, C26 USB_AVSS3 (power), D21 OTG_EXTR, D23 OTG_VBUS, E21 USB_AVDD_1V8 (power), F20 USB_AVDD_3V3 (power), G18 USB_AVDD_1V0 (power), H18 USB_AVSS1 (power)
part F pins: D28 GPIO7_A2_d (io), E26 GPIO7_A4_u (io), E27 GPS_MAG/HSADC_D0_T1/UART3_RX/GPIO7_A7_u (io), E28 eDP_HOTPLUG/GPIO7_B3_d (io), F25 GPIO7_A3_d (io), F26 GPIO7_A6_u (io), F27 UART3_RTSn/GPIO7_B2_u (io), F28 ISP_PRELIGHTTRIG/SPI1_RXD/GPIO7_B6_d (io), G23 PWM1/GPIO7_A1_d (io), G24 GPIO7_A5_d (io), G27 ISP_SHUTTERTRIG/SPI1_TXD/GPIO7_B7_d (io), G28 ISP_FLASHTRIGIN/EDPHDMI_CEC_T1/GPIO7_C0_u (io), H22 PWM0/GPIO7_A0_d (io), H23 GPS_RFCLK/GPS_CLK_T1/UART3_CTSn/GPIO7_B1_u (io), H24 ISP_FLASHTRIGOUT/SPI1_CSN0/GPIO7_B5_u (io), H25 I2C4_SDA/GPIO7_C1_u (io), H26 I2C5_SDA/EDPHDMI_I2C_SDA/GPIO7_C3_u (io), H27 GPIO7_C5_d (io), H28 UART2_TX/IR_TX/PWM3/EDPHDMI_CEC/GPIO7_C7_u (io), J21 GPS_SIG/HSADC_D1_T1/UART3_TX/GPIO7_B0_d (io), J22 ISP_SHUTTEREN/SPI1_CLK/GPIO7_B4_d (io), J23 I2C4_SCL/GPIO7_C2_u (io), J24 I2C5_SCL/EDPHDMI_I2C_SCL/GPIO7_C4_u (io), J25 UART2_RX/IR_RX/PWM2/GPIO7_C6_u (io), L20 APIO1_VDD (power)
part G pins: A28 I2C1_SDA/SC_RST/GPIO8_A4_u (io), B28 SPI2_CSn1/SC_IO/GPIO8_A3_u (io), C27 PS2_DATA/GPIO8_A1_u (io), C28 SPI2_TXD/SC_CLK_T1/GPIO8_B1_d (io), D24 PS2_CLK/GPIO8_A0_u (io), D26 SPI2_CLK/SC_IO_T1/GPIO8_A6_d (io), D27 SPI2_CSn0/SC_DET_T1/GPIO8_A7_u (io), E22 BS_JTAG_TRSTn (out), E23 BS_JTAG_TCK (out), E25 I2C1_SCL/SC_CLK/GPIO8_A5_u (io), F21 BS_JTAG_TDI (in), F22 BS_JTAG_TDO (out), F24 SPI2_RXD/SC_RST_T1/GPIO8_B0_d (io), G20 BS_JTAG_TMS (out), G21 SC_DET/GPIO8_A2_u (io), J20 APIO2_VDD (power)
part H pins: AA11 APIO3_VDD (power), AB11 UART0_RTSn/GPIO4_C3_u (io), AB12 UART0_CTSn/GPIO4_C2_u (io), AC11 SDIO0_PWR/GPIO4_D4_d (io), AD9 GPIO4_D7_u (io), AE8 SDIO0_INTn/GPIO4_D6_u (io), AE9 SDIO0_WP/GPIO4_D3_d (io), AF8 SDIO0_BKPWR/GPIO4_D5_d (io), AF9 SDIO0_DET/GPIO4_D2_u (io), AG8 SDIO0_CLKOUT/GPIO4_D1_d (io), AG9 SDIO0_D2/GPIO4_C6_u (io), AG10 UART0_TXD/GPIO4_C1_d (io), AH7 SDIO0_D3/GPIO4_C7_u (io), AH8 SDIO0_CMD/GPIO4_D0_u (io), AH9 SDIO0_D0/GPIO4_C4_u (io), AH10 SDIO0_D1/GPIO4_C5_u (io), AH11 UART0_RXD/GPIO4_C0_u (io)
part I pins: AC12 I2S_CLK/GPIO6_B0_d (io), AD11 I2S_SCLK/GPIO6_A0_d (io), AD12 I2C2_SCL/GPIO6_B2_u (io), AE11 I2S_SDI/GPIO6_A3_d (io), AE12 SPDIF_TX/GPIO6_B3_d (io), AF11 I2S_LRCK_TX/GPIO6_A2_d (io), AF12 I2C2_SDA/GPIO6_B1_u (io), AG11 I2S_LRCK_RX/GPIO6_A1_d (io), AG12 I2S_SDO0/GPIO6_A4_d (io), AG13 I2S_SDO2/GPIO6_A6_d (io), AH12 I2S_SDO3/GPIO6_A7_d (io), AH13 I2S_SDO1/GPIO6_A5_d (io), Y12 APIO4_VDD (power)
part J pins: AA7 UART1_TX/TS0_D1/GPIO5_B1_d (io), AA9 TS0_VALID/GPIO5_C1_d (io), AB8 TS0_ERR/GPIO5_C3_d (io), AC7 SPI0_CSn0/UART4_RTSn/TS0_D5/GPIO5_B5_u (io), AD6 UART1_RTSn/TS0_D3/GPIO5_B3_u (io), AD7 SPI0_CLK/UART4_CTSn/TS0_D4/GPIO5_B4_u (io), AE5 SPI0_TXD/UART4_TX/TS0_D6/GPIO5_B6_d (io), AE6 TS0_CLK/GPIO5_C2_d (io), AF5 UART1_RX/TS0_D0/GPIO5_B0_u (io), AF6 SPI0_RXD/UART4_RX/TS0_D7/GPIO5_B7_u (io), AG5 SPI0_CSn1/TS0_SYNC/GPIO5_C0_u (io), AH4 UART1_CTSn/TS0_D2/GPIO5_B2_u (io), Y11 APIO5_VDD (power)
part K pins: A1 DDR0_DQ25 (io), A2 DDR0_DQ24 (io), A3 DDR0_DQ10 (io), A4 DDR0_DQS3n (out), A5 DDR0_DQ9 (io), A6 DDR0_DQ13 (io), A7 DDR0_DQS1n (out), A8 DDR0_CASn (out), A9 DDR0_BA1 (out), A10 DDR0_A2 (out), A11 DDR0_CLKn (out), A12 DDR0_A7 (out), A13 DDR0_A10 (out), A14 DDR0_A9 (out), A15 DDR0_DM2 (out), A16 DDR0_DQ17 (io), A17 DDR0_DQS2n (out), A18 DDR0_DQ23 (io), A19 DDR0_DQ4 (io), A20 DDR0_DQS0 (out), B3 DDR0_DM3 (out), B4 DDR0_DQS3 (out), B5 DDR0_DQ8 (io), B6 DDR0_DQ14 (io), B7 DDR0_DQS1 (out), B8 DDR0_CSn0 (out), B9 DDR0_WEn (out), B10 DDR0_A0 (out), B11 DDR0_CLK (out), B12 DDR0_A5 (out), B13 DDR0_A8 (out), B14 DDR0_A14 (out), B15 DDR0_DQ16 (io), B16 DDR0_DQ19 (io), B17 DDR0_DQS2 (out), B18 DDR0_DQ21 (io), B19 DDR0_DQ0 (io), B20 DDR0_DQS0n (out), C4 DDR0_DQ30 (io), C5 DDR0_DQ28 (io), C6 DDR0_DQ11 (io), C8 DDR0_CKE1 (out), C9 DDR0_CKE0 (out), C11 DDR0_A1 (out), C12 DDR0_A6 (out), C14 DDR0_A13 (out), C15 DDR0_A15 (out), C17 DDR0_DQ22 (io), C18 DDR0_DQ1 (io), C20 DDR0_DQ6 (io), D5 DDR0_DQ26 (io), D8 DDR0_BA0 (out), D11 DDR0_RASn (out), D14 DDR0_A11 (out), D17 DDR0_DQ20 (io), D20 DDR0_DQ7 (io), E6 DDR0_DQ27 (io), E7 DDR0_DQ31 (io), E8 DDR0_DQ12 (io), E9 DDR0_RESET (out), E11 DDR0_BA2 (out), E12 DDR0_A3 (out), E14 DDR0_ODT0 (out), E15 DDR0_ODT1 (out), E17 DDR0_DM0 (out), E18 DDR0_DQ5 (io), F7 DDR0_DQ29 (io), F8 DDR0_DQ15 (io), F9 DDR0_DM1 (out), F11 DDR0_CSn1 (out), F12 DDR0_A4 (out), F14 DDR0_A12 (out), F15 DDR0_DQ18 (io), F17 DDR0_DQ2 (io), F18 DDR0_DQ3 (io), G8 DDR0_RETLE, G11 NC3, G12 DDR0_ATO, G14 NC1, G15 NC2, G17 DDR0_PZQ, H9 DDR0_VDD1 (power), H11 DDR0_VREFAO (power), H12 DDR0_VREF (power), H14 DDR0_VDDAO (power), H15 DDR0_DTO1, H17 DDR0_DTO0, J11 DDR0_VDD2 (power), J12 DDR0_VDD3 (power), J14 DDR0_VDD4 (power), J15 DDR0_VDD5 (power)
part L pins: AA1 DDR1_DQS0n (out), AA2 DDR1_DQS0 (out), B1 DDR1_DQ24 (io), B2 DDR1_DQ25 (io), C1 DDR1_DQ10 (io), C2 DDR1_DQ30 (io), D1 DDR1_DQS3n (out), D2 DDR1_DQS3 (out), D3 DDR1_DM3 (out), E1 DDR1_DQ9 (io), E2 DDR1_DQ8 (io), E3 DDR1_DQ28 (io), E4 DDR1_DQ26 (io), F1 DDR1_CKE0 (out), F2 DDR1_RESET (out), F3 DDR1_DQ11 (io), F5 DDR1_DQ29 (io), G1 DDR1_DQS1n (out), G2 DDR1_DQS1 (out), G5 DDR1_DM1 (out), G6 DDR1_DQ27 (io), H1 DDR1_CASn (out), H2 DDR1_CSn0 (out), H3 DDR1_CKE1 (out), H4 DDR1_DQ13 (io), H5 DDR1_DQ12 (io), H6 DDR1_DQ31 (io), H7 DDR1_RETLE, J1 DDR1_BA1 (out), J2 DDR1_WEn (out), J3 DDR1_CSn1 (out), J5 DDR1_DQ14 (io), J6 DDR1_DQ15 (io), J8 DDR1_VDD1 (power), K1 DDR1_A2 (out), K2 DDR1_A1 (out), L1 DDR1_CLKn (out), L2 DDR1_CLK (out), L3 DDR1_A0 (out), L4 DDR1_BA0 (out), L5 DDR1_BA2 (out), L6 DDR1_RASn (out), L7 NC6, L8 DDR1_VREFAO (power), L9 DDR1_VDD2 (power), M1 DDR1_A6 (out), M2 DDR1_A5 (out), M3 DDR1_A7 (out), M5 DDR1_A3 (out), M6 DDR1_A4 (out), M7 DDR1_ATO, M8 DDR1_VREF (power), M9 DDR1_VDD3 (power), N1 DDR1_A8 (out), N2 DDR1_A10 (out), P1 DDR1_A9 (out), P2 DDR1_A14 (out), P3 DDR1_A13 (out), P4 DDR1_A11 (out), P5 DDR1_ODT0 (out), P6 DDR1_A12 (out), P7 NC4, P8 DDR1_VDDAO (power), P9 DDR1_VDD4 (power), R1 DDR1_A15 (out), R2 DDR1_ODT1 (out), R3 DDR1_DM2 (out), R5 DDR1_DQ19 (io), R6 DDR1_DQ17 (io), R7 NC5, R8 DDR1_DTO1, R9 DDR1_VDD5 (power), T1 DDR1_DQ18 (io), T2 DDR1_DQ16 (io), U1 DDR1_DQS2n (out), U2 DDR1_DQS2 (out), U3 DDR1_DQ22 (io), U4 DDR1_DQ20 (io), U5 DDR1_DM0 (out), U6 DDR1_DQ3 (io), U7 DDR1_PZQ, U8 DDR1_DTO0, V1 DDR1_DQ21 (io), V2 DDR1_DQ23 (io), V3 DDR1_DQ1 (io), V5 DDR1_DQ6 (io), W1 DDR1_DQ4 (io), W2 DDR1_DQ0 (io), Y1 DDR1_DQ2 (io), Y2 DDR1_DQ5 (io), Y3 DDR1_DQ7 (io)
part M pins: A21 VSS9 (power), AC24 VSS11 (power), C3 VSS1 (power), D6 VSS2 (power), D9 VSS3 (power), D12 VSS4 (power), D15 VSS5 (power), D18 VSS6 (power), E20 VSS7 (power), F4 VSS12 (power), J4 VSS13 (power), J9 VSS14 (power), J17 VSS16 (power), J18 VSS28 (power), K10 VSS18 (power), K11 VSS19 (power), K12 VSS20 (power), K13 VSS21 (power), K14 VSS22 (power), K15 VSS23 (power), K16 VSS24 (power), K17 VSS25 (power), K18 VSS26 (power), K19 VSS27 (power), L10 VSS29 (power), L11 VSS30 (power), L13 VSS31 (power), L14 VSS32 (power), L15 VSS33 (power), M4 VSS34 (power), M10 VSS35 (power), M11 VSS36 (power), M13 VSS37 (power), M14 VSS38 (power), N10 VSS40 (power), N11 VSS41 (power), N13 VSS42 (power), N14 VSS43 (power), N15 VSS44 (power), P10 VSS45 (power), P11 VSS46 (power), P13 VSS47 (power), P14 VSS48 (power), P15 VSS49 (power), P16 VSS50 (power), P17 VSS51 (power), P18 VSS52 (power), R4 VSS53 (power), R10 VSS54 (power), R13 VSS55 (power), R14 VSS61 (power), R15 VSS71 (power), R16 VSS56 (power), R17 VSS57 (power), R18 VSS58 (power), R19 VSS59 (power), T10 VSS60 (power), T13 VSS62 (power), T15 VSS64 (power), T16 VSS65 (power), T17 VSS66 (power), T18 VSS67 (power), T19 VSS68 (power), U9 VSS15 (power), U10 VSS70 (power), U13 VSS72 (power), U24 VSS8 (power), V4 VSS73 (power), V9 VSS69 (power), V10 VSS74 (power), V11 VSS75 (power), V12 VSS76 (power), V13 VSS77 (power), W10 VSS17 (power), W11 VSS78 (power), W12 VSS79 (power), W13 VSS80 (power), W14 VSS81 (power), W15 VSS82 (power), W16 VSS83 (power), W17 VSS84 (power), W18 VSS85 (power), W19 VSS86 (power), Y18 VSS39 (power), Y20 VSS63 (power), Y24 VSS10 (power)
part N pins: AA12 eDP_TP_OUT, AA17 eDP_AVDD_1V8 (power), AC17 eDP_CLK24M_IN, AC18 eDP_EXTR, AG14 eDP_TX0P (out), AG15 eDP_TX1P (out), AG16 eDP_TX2P (out), AG17 eDP_TX3P (out), AG18 eDP_AXUP (out), AH14 eDP_TX0N (out), AH15 eDP_TX1N (out), AH16 eDP_TX2N (out), AH17 eDP_TX3N (out), AH18 eDP_AXUN (out), Y17 eDP_AVDD_1V0 (power)
part O pins: AA18 HDMI_AVDD_1V0 (power), AB17 HDMI_EXTR, AB18 HDMI_HPD_d, AB20 HDMI_AVDD_1V8 (power), AD20 AVSS5 (power), AD23 AVSS6 (power), AD26 AVSS7 (power), AF14 AVSS1 (power), AF15 AVSS2 (power), AF17 AVSS3 (power), AF18 AVSS4 (power), AF26 AVSS8 (power), AG19 HDMI_TXCP (out), AG20 HDMI_TX0P (out), AG21 HDMI_TX1P (out), AG22 HDMI_TX2P (out), AH19 HDMI_TXCN (out), AH20 HDMI_TX0N (out), AH21 HDMI_TX1N (out), AH22 HDMI_TX2N (out)
part P pins: AB6 FLASH0_DQS/EMMC_CLKOUT/GPIO3_C2_d (io), AC4 FLASH0_CSn2/EMMC_CMD/GPIO3_C0_u (io), AC5 FLASH0_CSn0/GPIO3_B6_u (io), AD3 FLASH0_D1/EMMC_D1/GPIO3_A1_u (io), AD4 FLASH0_CSn1/GPIO3_B7_u (io), AE3 FLASH0_D0/EMMC_D0/GPIO3_A0_u (io), AF1 FLASH0_D3/EMMC_D3/GPIO3_A3_u (io), AF2 FLASH0_D4/EMMC_D4/GPIO3_A4_u (io), AF3 FLASH0_D2/EMMC_D2/GPIO3_A2_u (io), AF4 FLASH0_ALE/GPIO3_B3_d (io), AG1 FLASH0_D6/EMMC_D6/GPIO3_A6_u (io), AG2 FLASH0_D7/EMMC_D7/GPIO3_A7_u (io), AG3 FLASH0_D5/EMMC_D5/GPIO3_A5_u (io), AG4 FLASH0_WRN/GPIO3_B5_u (io), AH1 FLASH0_WP/EMMC_PWREN/GPIO3_B1_d (io), AH2 FLASH0_RDY/GPIO3_B0_u (io), AH3 FLASH0_CLE/GPIO3_B4_d (io), Y6 FLASH0_RDN/GPIO3_B2_u (io), Y7 FLASH0_CSn3/EMMC_RSTNOUT/GPIO3_C1_u (io), Y8 FLASH0_VOLTAGE_SEL/GPIO3_C3_d (io), Y9 FLASH0_VDD (power)
part Q pins: AA3 HOST_D6/MAC_RXD0/SDIO1_BKPWR/FLASH1_D6/GPIO3_D6_u (io), AA4 HOST_D7/MAC_RXD1/SDIO1_INTn/FLASH1_D7/GPIO3_D7_u (io), AA5 HOST_D14/MAC_COL/FLASH1_DQS/FLASH1_CSn3/GPIO4_B0_u (io), AA6 HOST_D13/MAC_CRS/SDIO1_CLKOUT/FLASH1_CSn1/GPIO4_A7_u (io), AB1 HOST_D2/MAC_RXD2/SDIO1_D2/FLASH1_D2/GPIO3_D2_u (io), AB2 HOST_D5/MAC_TXD1/SDIO1_WRPRT/FLASH1_D5/GPIO3_D5_u (io), AB5 HOST_D12/MAC_RXCLK/SDIO1_CMD/FLASH1_CSn0/GPIO4_A6_u (io), AC1 HOST_D3/MAC_RXD3/SDIO1_D3/FLASH1_D3/GPIO3_D3_u (io), AC2 HOST_CKOUTN/MAC_RXDV/FLASH0_CSn4/FLASH1_WP/GPIO4_A1_u (io), AC3 HOST_CKOUTP/MAC_MDC/FLASH1_RDY/GPIO4_A0_u (io), AD1 HOST_D4/MAC_TXD0/SDIO1_DET/FLASH1_D4/GPIO3_D4_u (io), AD2 HOST_D10/MAC_TXEN/FLASH0_CSn7/FLASH1_CLE/GPIO4_A4_u (io), AE1 HOST_D8/MAC_RXER/FLASH0_CSn5/FLASH1_RDN/GPIO4_A2_u (io), AE2 HOST_D9/MAC_CLK/FLASH0_CSn6/FLASH1_ALE/GPIO4_A3_u (io), V6 HOST_D1/MAC_TXD3/SDIO1_D1/FLASH1_D1/GPIO3_D1_u (io), V7 HOST_D15/MAC_TXCLK/SDIO1_PWREN/FLASH1_CSn2/GPIO4_B1_u (io), V8 FLASH1_VDD (power), Y4 HOST_D0/MAC_TXD2/SDIO1_D0/FLASH1_D0/GPIO3_D0_u (io), Y5 HOST_D11/MAC_MDIO/FLASH1_WRN/GPIO4_A5_u (io)
part R pins: L12 LOGIC_VDD1 (power), L16 GPU_VDD1 (power), L17 GPU_VDD2 (power), L18 GPU_VDD3 (power), L19 GPU_VDD4 (power), M12 LOGIC_VDD2 (power), M15 GPU_VDD_COM, M16 GPU_VDD5 (power), M17 GPU_VDD6 (power), M18 GPU_VDD7 (power), M19 GPU_VDD8 (power), N12 LOGIC_VDD3 (power), N16 GPU_VDD9 (power), N17 GPU_VDD10 (power), N18 GPU_VDD11 (power), N19 GPU_VDD12 (power), P12 LOGIC_VDD4 (power), R11 LOGIC_VDD8 (power), R12 LOGIC_VDD5 (power), T11 LOGIC_VDD9 (power), T12 LOGIC_VDD6 (power), T14 CPU_VDD_COM, U11 LOGIC_VDD10 (power), U12 LOGIC_VDD7 (power), U14 CPU_VDD1 (power), U15 CPU_VDD2 (power), U16 CPU_VDD3 (power), U17 CPU_VDD4 (power), U18 CPU_VDD5 (power), U19 CPU_VDD6 (power), V14 CPU_VDD7 (power), V15 CPU_VDD8 (power), V16 CPU_VDD9 (power), V17 CPU_VDD10 (power), V18 CPU_VDD11 (power), V19 CPU_VDD12 (power), V20 LCDC_VDD (power)
part S pins: A24 NC11 (in), A25 NC9 (out), AA14 NC28 (power), AA15 NC18 (power), AB14 NC14 (out), AB15 NC13 (out), AC14 NC16 (in), AC15 NC15 (in), AD14 NC20 (in), AD15 NC24 (out), AD17 NC22 (in), AD18 NC26 (out), AE14 NC19 (in), AE15 NC23 (out), AE17 NC21 (in), AE18 NC25 (out), B24 NC12 (in), B25 NC10 (out), G9 NC7, J7 NC8, Y14 NC27 (power), Y15 NC17 (power)
part T pins: P21 RECOVER/ADC_IN1 (in), P23 ADC_IN2 (in), P24 ADC_IN0 (in), R20 ADC_AVDD_1V8 (power)
part U pins: A27 HSIC_DATA, B27 HSIC_STROBE, H20 HSIC_AVDD_1V2 (power)
part V pins: AC22 MIPI_TX_AVDD_1V8 (power), AC27 MIPI_TX_D3P (out), AC28 MIPI_TX_D3N (out), AD27 MIPI_TX_D2P (out), AD28 MIPI_TX_D2N (out), AE26 MIPI_TX_REXT, AE27 MIPI_TX_CLKP (out), AE28 MIPI_TX_CLKN (out), AF27 MIPI_TX_D1P (out), AF28 MIPI_TX_D1N (out), AG27 MIPI_TX_D0P (out), AG28 MIPI_TX_D0N (out)
part W pins: AC20 MIPI_RX_AVDD_1V8 (power), AD21 MIPI_RX_REXT, AG23 MIPI_RX_D0P (in), AG24 MIPI_RX_D1P (in), AG25 MIPI_RX_CLKP (in), AG26 MIPI_RX_D2P (in), AH23 MIPI_RX_D0N (in), AH24 MIPI_RX_D1N (in), AH25 MIPI_RX_CLKN (in), AH26 MIPI_RX_D2N (in), AH27 MIPI_RX_D3N (in), AH28 MIPI_RX_D3P (in)
part X pins: AC21 MIPI_TX/RX_AVDD_1V8 (power), AD22 MIPI_TX/RX_REXT, AD25 MIPI_TX/RX_D3N (io), AE20 MIPI_TX/RX_D0P (io), AE21 MIPI_TX/RX_D1P (io), AE23 MIPI_TX/RX_CLKP (io), AE24 MIPI_TX/RX_D2P (io), AF20 MIPI_TX/RX_D0N (io), AF21 MIPI_TX/RX_D1N (io), AF23 MIPI_TX/RX_CLKN (io), AF24 MIPI_TX/RX_D2N (io), AF25 MIPI_TX/RX_D3P (io)

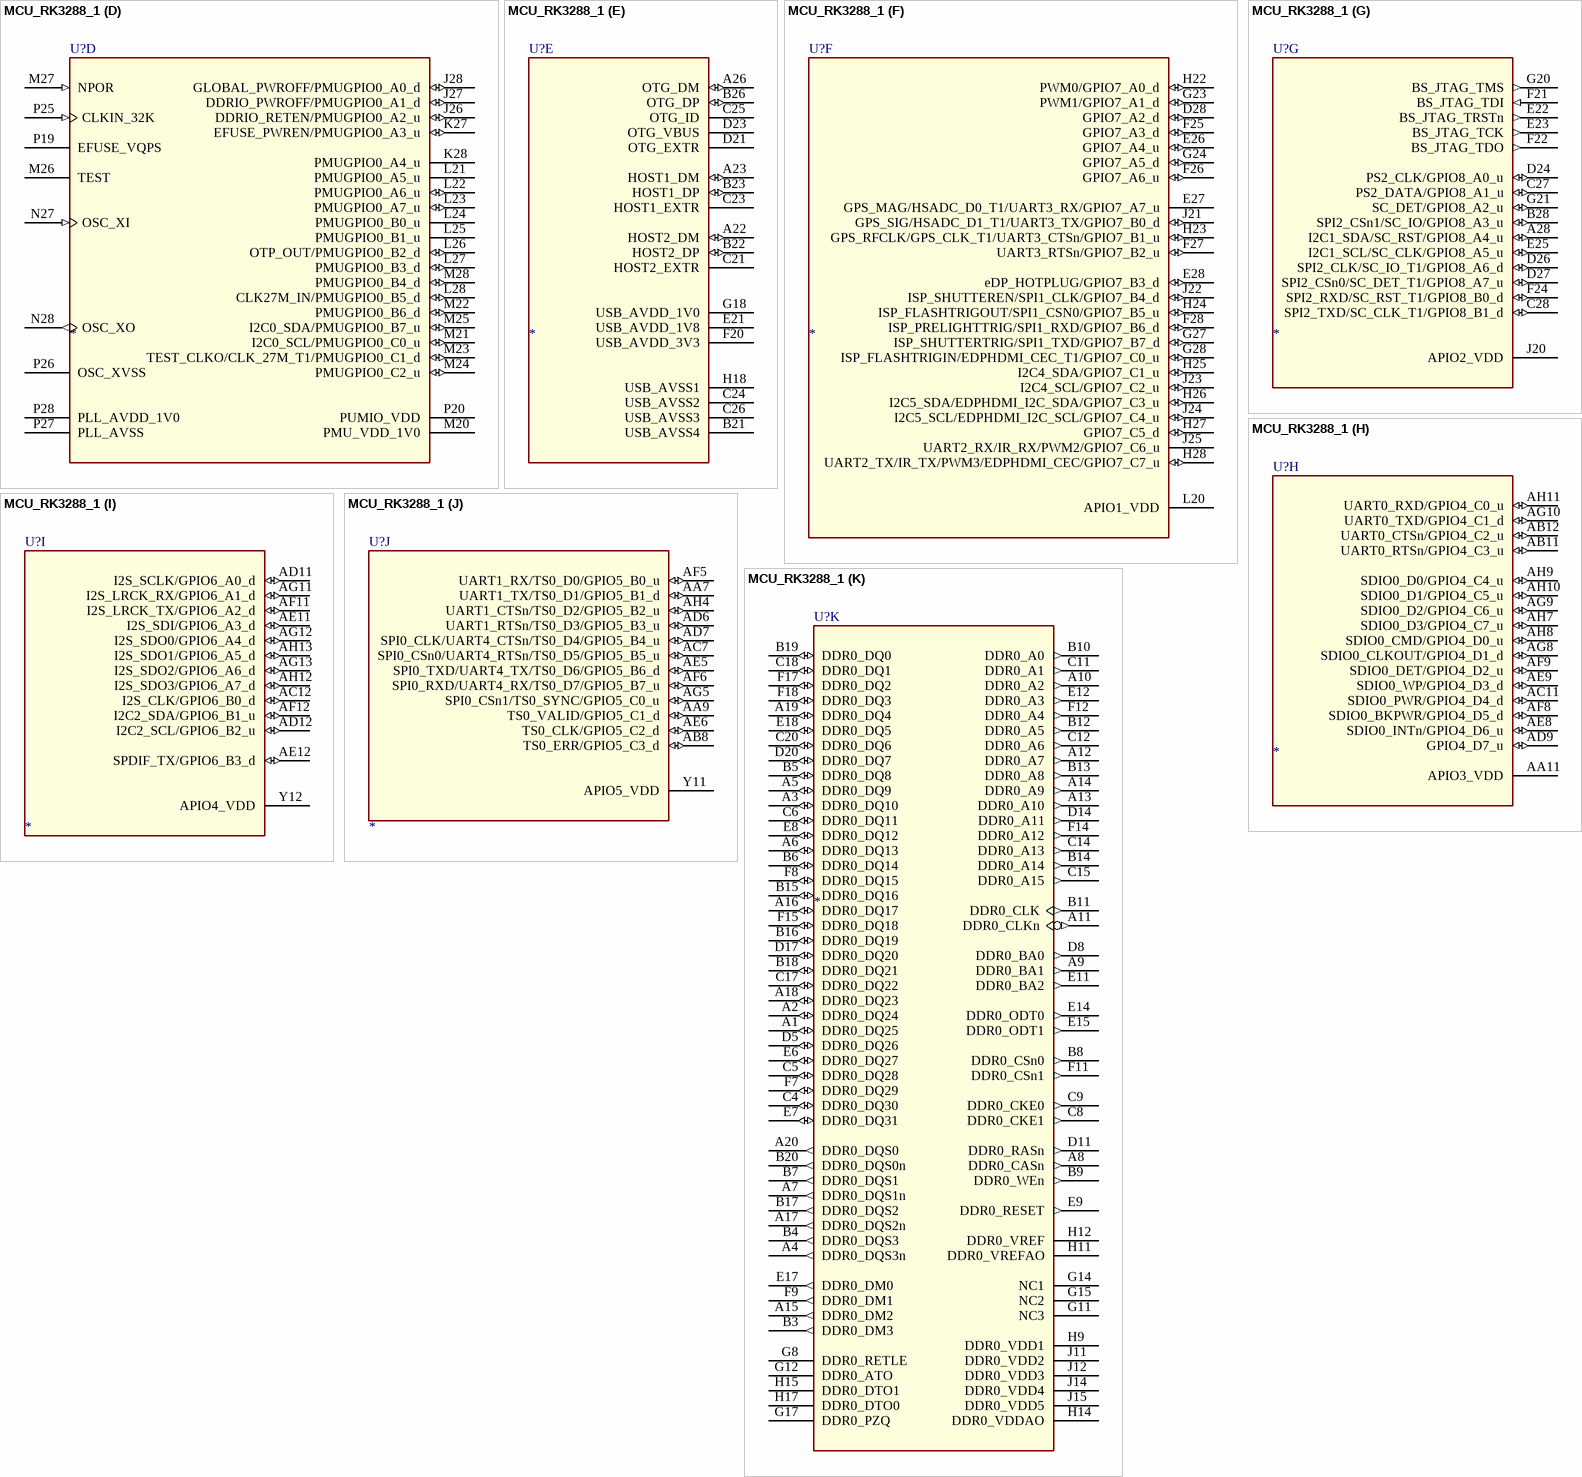
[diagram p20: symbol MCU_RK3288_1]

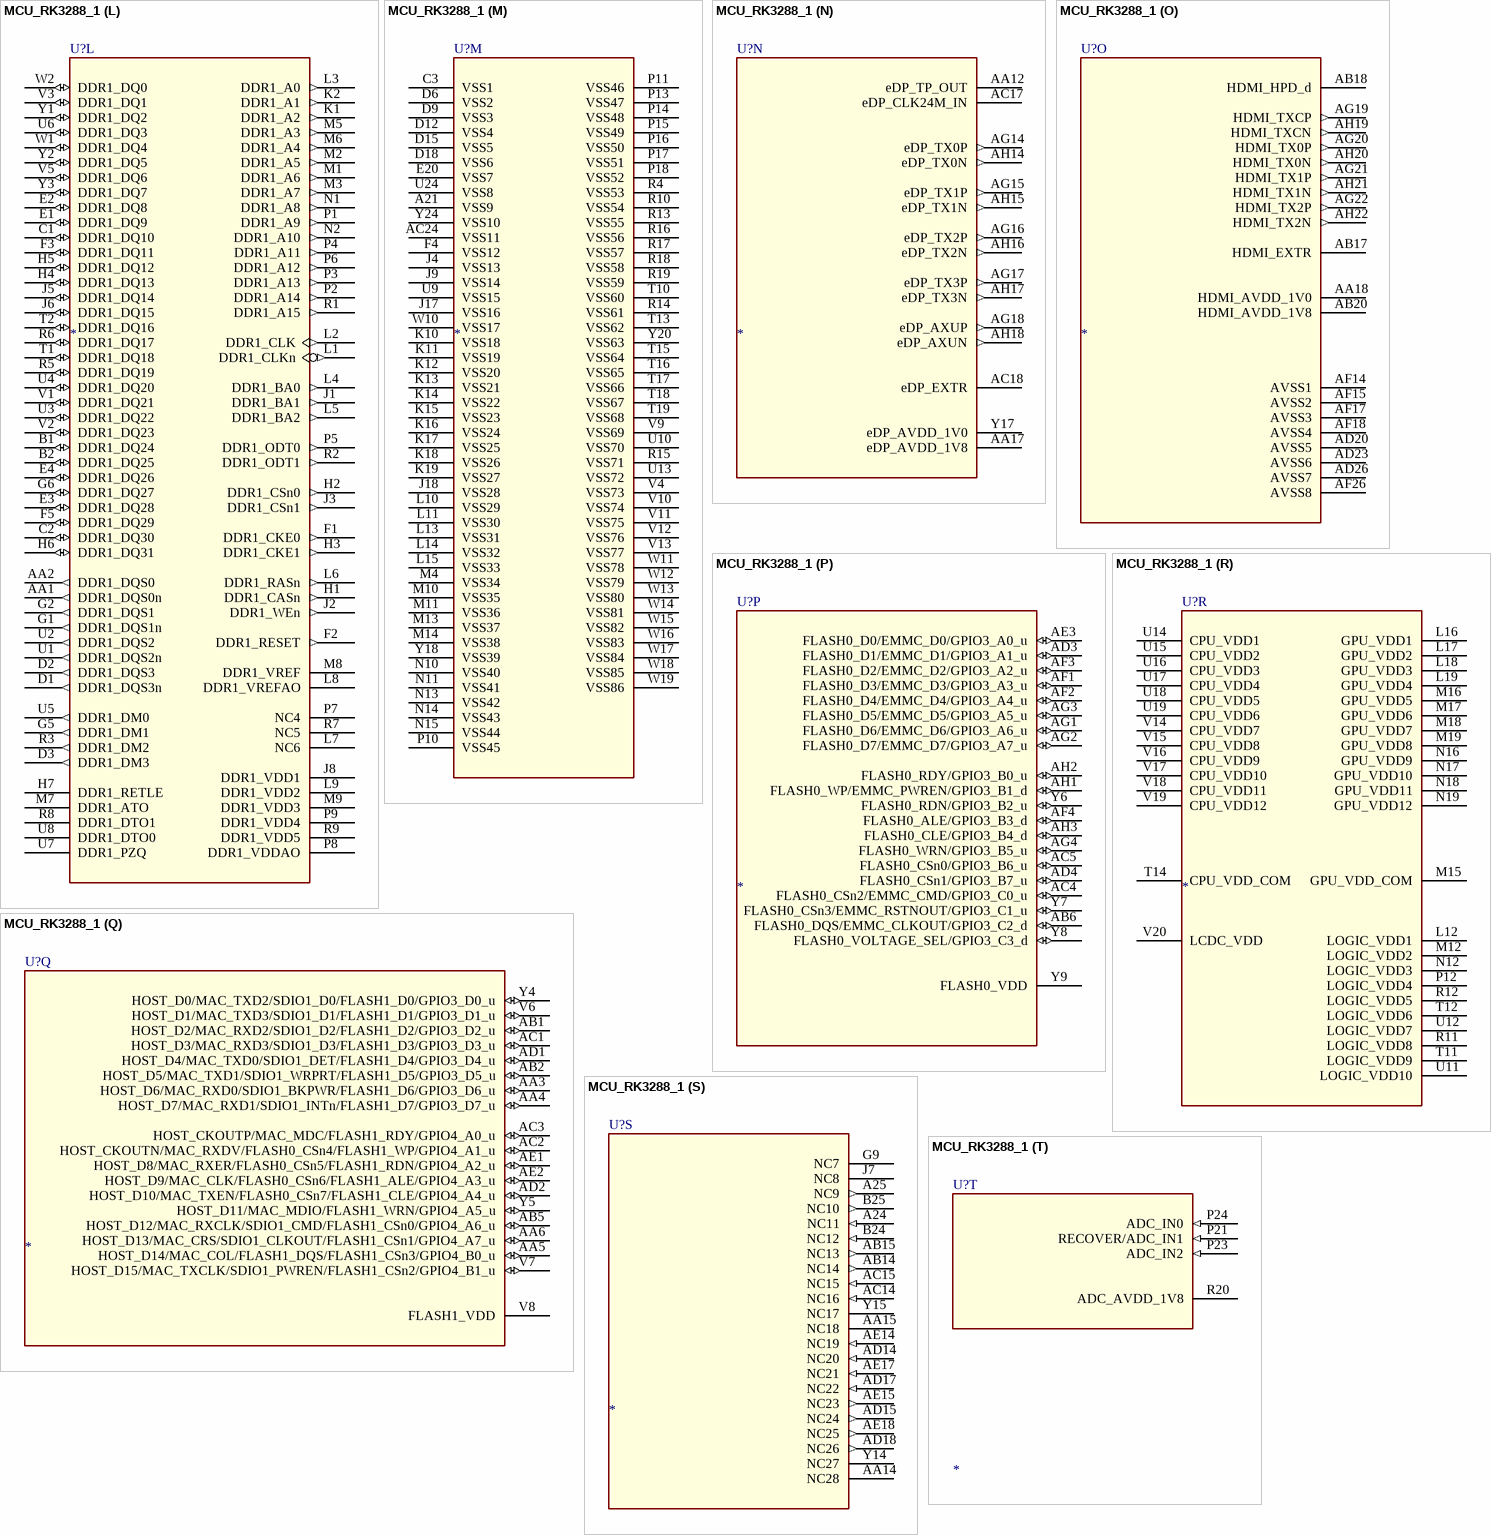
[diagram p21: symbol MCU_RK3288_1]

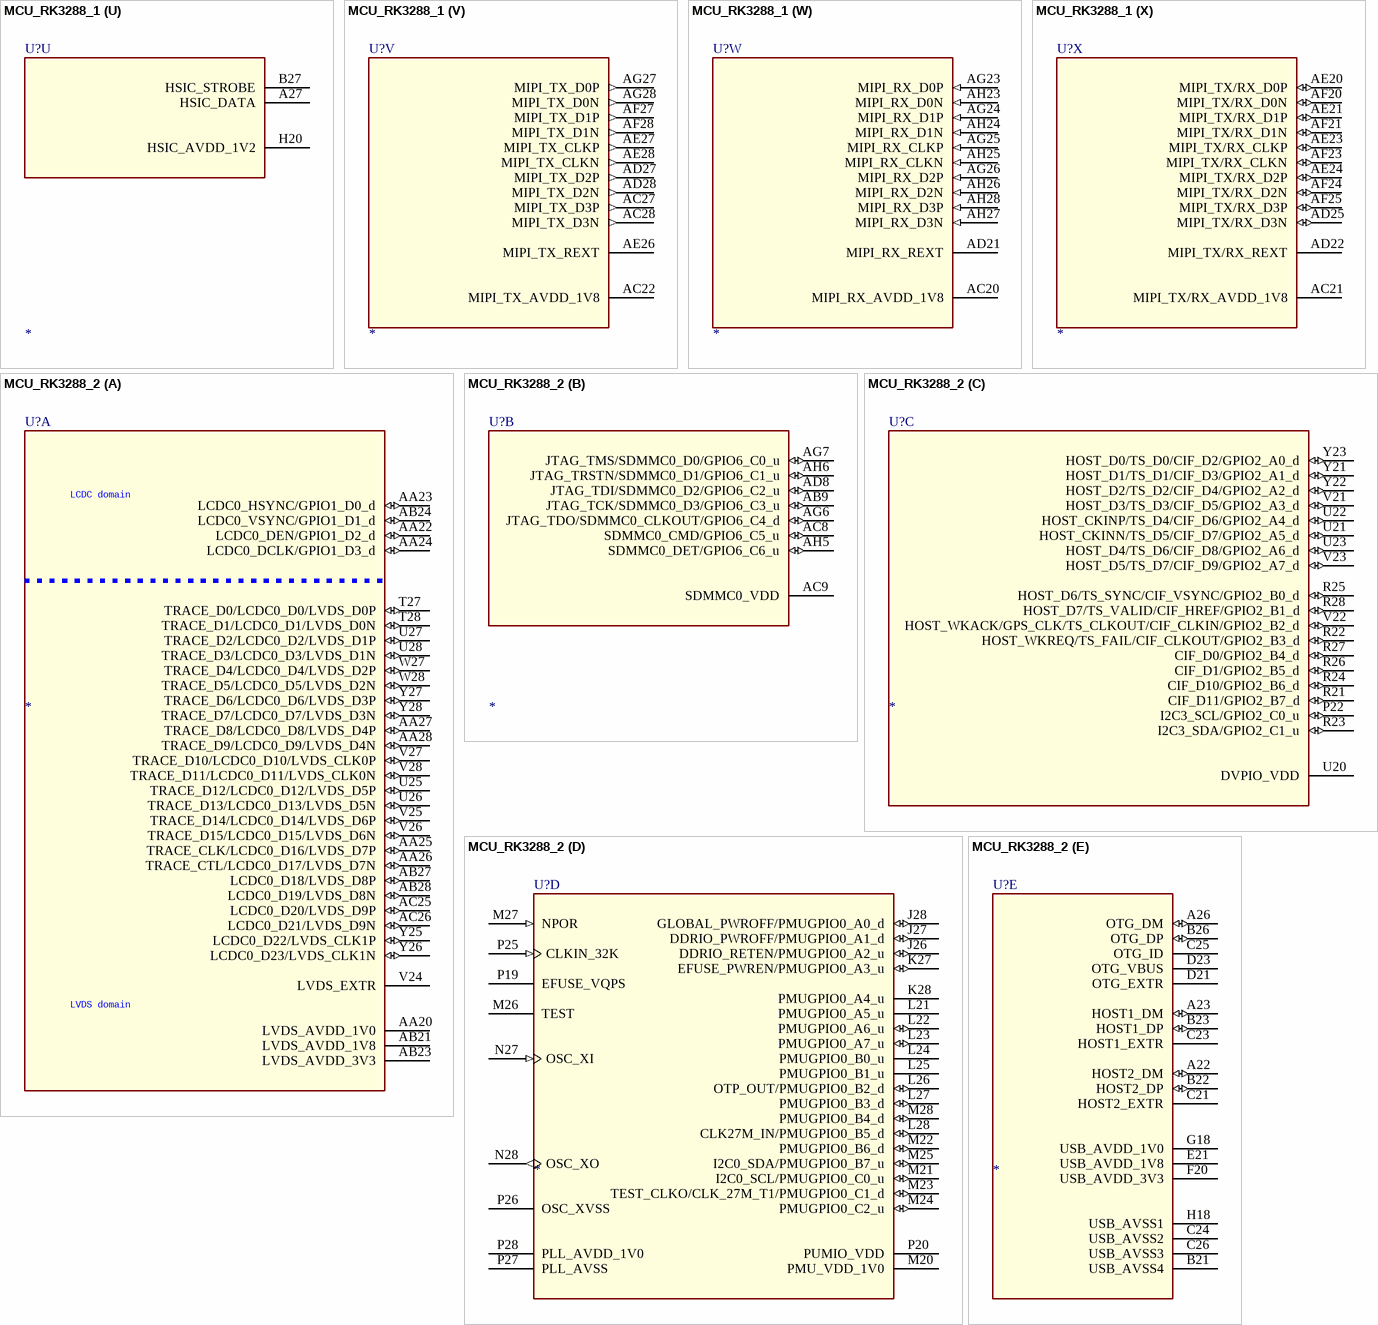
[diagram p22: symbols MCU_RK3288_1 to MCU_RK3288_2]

## MCU_RK3288_1
designator U?
footprint BGA453-19X19
part A pins: AA20 LVDS_AVDD_1V0 (power), AA22 LCDC0_DEN/GPIO1_D2_d (io), AA23 LCDC0_HSYNC/GPIO1_D0_d (io), AA24 LCDC0_DCLK/GPIO1_D3_d (io), AA25 TRACE_CLK/LCDC0_D16/LVDS_D7P (io), AA26 TRACE_CTL/LCDC0_D17/LVDS_D7N (io), AA27 TRACE_D8/LCDC0_D8/LVDS_D4P (io), AA28 TRACE_D9/LCDC0_D9/LVDS_D4N (io), AB21 LVDS_AVDD_1V8 (power), AB23 LVDS_AVDD_3V3 (power), AB24 LCDC0_VSYNC/GPIO1_D1_d (io), AB27 LCDC0_D18/LVDS_D8P (io), AB28 LCDC0_D19/LVDS_D8N (io), AC25 LCDC0_D20/LVDS_D9P (io), AC26 LCDC0_D21/LVDS_D9N (io), T27 TRACE_D0/LCDC0_D0/LVDS_D0P (io), T28 TRACE_D1/LCDC0_D1/LVDS_D0N (io), U25 TRACE_D12/LCDC0_D12/LVDS_D5P (io), U26 TRACE_D13/LCDC0_D13/LVDS_D5N (io), U27 TRACE_D2/LCDC0_D2/LVDS_D1P (io), U28 TRACE_D3/LCDC0_D3/LVDS_D1N (io), V24 LVDS_EXTR, V25 TRACE_D14/LCDC0_D14/LVDS_D6P (io), V26 TRACE_D15/LCDC0_D15/LVDS_D6N (io), V27 TRACE_D10/LCDC0_D10/LVDS_CLK0P (io), V28 TRACE_D11/LCDC0_D11/LVDS_CLK0N (io), W27 TRACE_D4/LCDC0_D4/LVDS_D2P (io), W28 TRACE_D5/LCDC0_D5/LVDS_D2N (io), Y25 LCDC0_D22/LVDS_CLK1P (io), Y26 LCDC0_D23/LVDS_CLK1N (io), Y27 TRACE_D6/LCDC0_D6/LVDS_D3P (io), Y28 TRACE_D7/LCDC0_D7/LVDS_D3N (io)
part B pins: AB9 JTAG_TCK/SDMMC0_D3/GPIO6_C3_u (io), AC8 SDMMC0_CMD/GPIO6_C5_u (io), AC9 SDMMC0_VDD (power), AD8 JTAG_TDI/SDMMC0_D2/GPIO6_C2_u (io), AG6 JTAG_TDO/SDMMC0_CLKOUT/GPIO6_C4_d (io), AG7 JTAG_TMS/SDMMC0_D0/GPIO6_C0_u (io), AH5 SDMMC0_DET/GPIO6_C6_u (io), AH6 JTAG_TRSTN/SDMMC0_D1/GPIO6_C1_u (io)
part C pins: P22 I2C3_SCL/GPIO2_C0_u (io), R21 CIF_D11/GPIO2_B7_d (io), R22 HOST_WKREQ/TS_FAIL/CIF_CLKOUT/GPIO2_B3_d (io), R23 I2C3_SDA/GPIO2_C1_u (io), R24 CIF_D10/GPIO2_B6_d (io), R25 HOST_D6/TS_SYNC/CIF_VSYNC/GPIO2_B0_d (io), R26 CIF_D1/GPIO2_B5_d (io), R27 CIF_D0/GPIO2_B4_d (io), R28 HOST_D7/TS_VALID/CIF_HREF/GPIO2_B1_d (io), U20 DVPIO_VDD (power), U21 HOST_CKINN/TS_D5/CIF_D7/GPIO2_A5_d (io), U22 HOST_CKINP/TS_D4/CIF_D6/GPIO2_A4_d (io), U23 HOST_D4/TS_D6/CIF_D8/GPIO2_A6_d (io), V21 HOST_D3/TS_D3/CIF_D5/GPIO2_A3_d (io), V22 HOST_WKACK/GPS_CLK/TS_CLKOUT/CIF_CLKIN/GPIO2_B2_d (io), V23 HOST_D5/TS_D7/CIF_D9/GPIO2_A7_d (io), Y21 HOST_D1/TS_D1/CIF_D3/GPIO2_A1_d (io), Y22 HOST_D2/TS_D2/CIF_D4/GPIO2_A2_d (io), Y23 HOST_D0/TS_D0/CIF_D2/GPIO2_A0_d (io)
part D pins: J26 DDRIO_RETEN/PMUGPIO0_A2_u (io), J27 DDRIO_PWROFF/PMUGPIO0_A1_d (io), J28 GLOBAL_PWROFF/PMUGPIO0_A0_d (io), K27 EFUSE_PWREN/PMUGPIO0_A3_u (io), K28 PMUGPIO0_A4_u, L21 PMUGPIO0_A5_u, L22 PMUGPIO0_A6_u (io), L23 PMUGPIO0_A7_u (io), L24 PMUGPIO0_B0_u, L25 PMUGPIO0_B1_u, L26 OTP_OUT/PMUGPIO0_B2_d (io), L27 PMUGPIO0_B3_d (io), L28 CLK27M_IN/PMUGPIO0_B5_d (io), M20 PMU_VDD_1V0 (power), M21 I2C0_SCL/PMUGPIO0_C0_u (io), M22 PMUGPIO0_B6_d (io), M23 TEST_CLKO/CLK_27M_T1/PMUGPIO0_C1_d (io), M24 PMUGPIO0_C2_u (io), M25 I2C0_SDA/PMUGPIO0_B7_u (io), M26 TEST, M27 NPOR (in), M28 PMUGPIO0_B4_d (io), N27 OSC_XI (in), N28 OSC_XO (out), P19 EFUSE_VQPS (power), P20 PUMIO_VDD (power), P25 CLKIN_32K (in), P26 OSC_XVSS (power), P27 PLL_AVSS (power), P28 PLL_AVDD_1V0 (power)
part E pins: A22 HOST2_DM (io), A23 HOST1_DM (io), A26 OTG_DM (io), B21 USB_AVSS4 (power), B22 HOST2_DP (io), B23 HOST1_DP (io), B26 OTG_DP (io), C21 HOST2_EXTR, C23 HOST1_EXTR, C24 USB_AVSS2 (power), C25 OTG_ID, C26 USB_AVSS3 (power), D21 OTG_EXTR, D23 OTG_VBUS, E21 USB_AVDD_1V8 (power), F20 USB_AVDD_3V3 (power), G18 USB_AVDD_1V0 (power), H18 USB_AVSS1 (power)
part F pins: D28 GPIO7_A2_d (io), E26 GPIO7_A4_u (io), E27 GPS_MAG/HSADC_D0_T1/UART3_RX/GPIO7_A7_u, E28 eDP_HOTPLUG/GPIO7_B3_d (io), F25 GPIO7_A3_d (io), F26 GPIO7_A6_u (io), F27 UART3_RTSn/GPIO7_B2_u (io), F28 ISP_PRELIGHTTRIG/SPI1_RXD/GPIO7_B6_d (io), G23 PWM1/GPIO7_A1_d (io), G24 GPIO7_A5_d (io), G27 ISP_SHUTTERTRIG/SPI1_TXD/GPIO7_B7_d (io), G28 ISP_FLASHTRIGIN/EDPHDMI_CEC_T1/GPIO7_C0_u (io), H22 PWM0/GPIO7_A0_d (io), H23 GPS_RFCLK/GPS_CLK_T1/UART3_CTSn/GPIO7_B1_u (io), H24 ISP_FLASHTRIGOUT/SPI1_CSN0/GPIO7_B5_u (io), H25 I2C4_SDA/GPIO7_C1_u (io), H26 I2C5_SDA/EDPHDMI_I2C_SDA/GPIO7_C3_u (io), H27 GPIO7_C5_d (io), H28 UART2_TX/IR_TX/PWM3/EDPHDMI_CEC/GPIO7_C7_u (io), J21 GPS_SIG/HSADC_D1_T1/UART3_TX/GPIO7_B0_d (io), J22 ISP_SHUTTEREN/SPI1_CLK/GPIO7_B4_d (io), J23 I2C4_SCL/GPIO7_C2_u (io), J24 I2C5_SCL/EDPHDMI_I2C_SCL/GPIO7_C4_u (io), J25 UART2_RX/IR_RX/PWM2/GPIO7_C6_u, L20 APIO1_VDD (power)
part G pins: A28 I2C1_SDA/SC_RST/GPIO8_A4_u (io), B28 SPI2_CSn1/SC_IO/GPIO8_A3_u (io), C27 PS2_DATA/GPIO8_A1_u (io), C28 SPI2_TXD/SC_CLK_T1/GPIO8_B1_d (io), D24 PS2_CLK/GPIO8_A0_u (io), D26 SPI2_CLK/SC_IO_T1/GPIO8_A6_d (io), D27 SPI2_CSn0/SC_DET_T1/GPIO8_A7_u (io), E22 BS_JTAG_TRSTn (out), E23 BS_JTAG_TCK (out), E25 I2C1_SCL/SC_CLK/GPIO8_A5_u (io), F21 BS_JTAG_TDI (in), F22 BS_JTAG_TDO (out), F24 SPI2_RXD/SC_RST_T1/GPIO8_B0_d (io), G20 BS_JTAG_TMS (out), G21 SC_DET/GPIO8_A2_u (io), J20 APIO2_VDD (power)
part H pins: AA11 APIO3_VDD (power), AB11 UART0_RTSn/GPIO4_C3_u (io), AB12 UART0_CTSn/GPIO4_C2_u (io), AC11 SDIO0_PWR/GPIO4_D4_d (io), AD9 GPIO4_D7_u (io), AE8 SDIO0_INTn/GPIO4_D6_u (io), AE9 SDIO0_WP/GPIO4_D3_d (io), AF8 SDIO0_BKPWR/GPIO4_D5_d (io), AF9 SDIO0_DET/GPIO4_D2_u (io), AG8 SDIO0_CLKOUT/GPIO4_D1_d (io), AG9 SDIO0_D2/GPIO4_C6_u (io), AG10 UART0_TXD/GPIO4_C1_d (io), AH7 SDIO0_D3/GPIO4_C7_u (io), AH8 SDIO0_CMD/GPIO4_D0_u (io), AH9 SDIO0_D0/GPIO4_C4_u (io), AH10 SDIO0_D1/GPIO4_C5_u (io), AH11 UART0_RXD/GPIO4_C0_u (io)
part I pins: AC12 I2S_CLK/GPIO6_B0_d (io), AD11 I2S_SCLK/GPIO6_A0_d (io), AD12 I2C2_SCL/GPIO6_B2_u (io), AE11 I2S_SDI/GPIO6_A3_d (io), AE12 SPDIF_TX/GPIO6_B3_d (io), AF11 I2S_LRCK_TX/GPIO6_A2_d (io), AF12 I2C2_SDA/GPIO6_B1_u (io), AG11 I2S_LRCK_RX/GPIO6_A1_d (io), AG12 I2S_SDO0/GPIO6_A4_d (io), AG13 I2S_SDO2/GPIO6_A6_d (io), AH12 I2S_SDO3/GPIO6_A7_d (io), AH13 I2S_SDO1/GPIO6_A5_d (io), Y12 APIO4_VDD (power)
part J pins: AA7 UART1_TX/TS0_D1/GPIO5_B1_d (io), AA9 TS0_VALID/GPIO5_C1_d (io), AB8 TS0_ERR/GPIO5_C3_d (io), AC7 SPI0_CSn0/UART4_RTSn/TS0_D5/GPIO5_B5_u (io), AD6 UART1_RTSn/TS0_D3/GPIO5_B3_u (io), AD7 SPI0_CLK/UART4_CTSn/TS0_D4/GPIO5_B4_u (io), AE5 SPI0_TXD/UART4_TX/TS0_D6/GPIO5_B6_d (io), AE6 TS0_CLK/GPIO5_C2_d (io), AF5 UART1_RX/TS0_D0/GPIO5_B0_u (io), AF6 SPI0_RXD/UART4_RX/TS0_D7/GPIO5_B7_u (io), AG5 SPI0_CSn1/TS0_SYNC/GPIO5_C0_u (io), AH4 UART1_CTSn/TS0_D2/GPIO5_B2_u (io), Y11 APIO5_VDD (power)
part K pins: A1 DDR0_DQ25 (io), A2 DDR0_DQ24 (io), A3 DDR0_DQ10 (io), A4 DDR0_DQS3n (out), A5 DDR0_DQ9 (io), A6 DDR0_DQ13 (io), A7 DDR0_DQS1n (out), A8 DDR0_CASn (out), A9 DDR0_BA1 (out), A10 DDR0_A2 (out), A11 DDR0_CLKn (out), A12 DDR0_A7 (out), A13 DDR0_A10 (out), A14 DDR0_A9 (out), A15 DDR0_DM2 (out), A16 DDR0_DQ17 (io), A17 DDR0_DQS2n (out), A18 DDR0_DQ23 (io), A19 DDR0_DQ4 (io), A20 DDR0_DQS0 (out), B3 DDR0_DM3 (out), B4 DDR0_DQS3 (out), B5 DDR0_DQ8 (io), B6 DDR0_DQ14 (io), B7 DDR0_DQS1 (out), B8 DDR0_CSn0 (out), B9 DDR0_WEn (out), B10 DDR0_A0 (out), B11 DDR0_CLK (out), B12 DDR0_A5 (out), B13 DDR0_A8 (out), B14 DDR0_A14 (out), B15 DDR0_DQ16 (io), B16 DDR0_DQ19 (io), B17 DDR0_DQS2 (out), B18 DDR0_DQ21 (io), B19 DDR0_DQ0 (io), B20 DDR0_DQS0n (out), C4 DDR0_DQ30 (io), C5 DDR0_DQ28 (io), C6 DDR0_DQ11 (io), C8 DDR0_CKE1 (out), C9 DDR0_CKE0 (out), C11 DDR0_A1 (out), C12 DDR0_A6 (out), C14 DDR0_A13 (out), C15 DDR0_A15 (out), C17 DDR0_DQ22 (io), C18 DDR0_DQ1 (io), C20 DDR0_DQ6 (io), D5 DDR0_DQ26 (io), D8 DDR0_BA0 (out), D11 DDR0_RASn (out), D14 DDR0_A11 (out), D17 DDR0_DQ20 (io), D20 DDR0_DQ7 (io), E6 DDR0_DQ27 (io), E7 DDR0_DQ31 (io), E8 DDR0_DQ12 (io), E9 DDR0_RESET (out), E11 DDR0_BA2 (out), E12 DDR0_A3 (out), E14 DDR0_ODT0 (out), E15 DDR0_ODT1 (out), E17 DDR0_DM0 (out), E18 DDR0_DQ5 (io), F7 DDR0_DQ29 (io), F8 DDR0_DQ15 (io), F9 DDR0_DM1 (out), F11 DDR0_CSn1 (out), F12 DDR0_A4 (out), F14 DDR0_A12 (out), F15 DDR0_DQ18 (io), F17 DDR0_DQ2 (io), F18 DDR0_DQ3 (io), G8 DDR0_RETLE, G11 NC3, G12 DDR0_ATO, G14 NC1, G15 NC2, G17 DDR0_PZQ, H9 DDR0_VDD1 (power), H11 DDR0_VREFAO (power), H12 DDR0_VREF (power), H14 DDR0_VDDAO (power), H15 DDR0_DTO1, H17 DDR0_DTO0, J11 DDR0_VDD2 (power), J12 DDR0_VDD3 (power), J14 DDR0_VDD4 (power), J15 DDR0_VDD5 (power)
part L pins: AA1 DDR1_DQS0n (out), AA2 DDR1_DQS0 (out), B1 DDR1_DQ24 (io), B2 DDR1_DQ25 (io), C1 DDR1_DQ10 (io), C2 DDR1_DQ30 (io), D1 DDR1_DQS3n (out), D2 DDR1_DQS3 (out), D3 DDR1_DM3 (out), E1 DDR1_DQ9 (io), E2 DDR1_DQ8 (io), E3 DDR1_DQ28 (io), E4 DDR1_DQ26 (io), F1 DDR1_CKE0 (out), F2 DDR1_RESET (out), F3 DDR1_DQ11 (io), F5 DDR1_DQ29 (io), G1 DDR1_DQS1n (out), G2 DDR1_DQS1 (out), G5 DDR1_DM1 (out), G6 DDR1_DQ27 (io), H1 DDR1_CASn (out), H2 DDR1_CSn0 (out), H3 DDR1_CKE1 (out), H4 DDR1_DQ13 (io), H5 DDR1_DQ12 (io), H6 DDR1_DQ31 (io), H7 DDR1_RETLE, J1 DDR1_BA1 (out), J2 DDR1_WEn (out), J3 DDR1_CSn1 (out), J5 DDR1_DQ14 (io), J6 DDR1_DQ15 (io), J8 DDR1_VDD1 (power), K1 DDR1_A2 (out), K2 DDR1_A1 (out), L1 DDR1_CLKn (out), L2 DDR1_CLK (out), L3 DDR1_A0 (out), L4 DDR1_BA0 (out), L5 DDR1_BA2 (out), L6 DDR1_RASn (out), L7 NC6, L8 DDR1_VREFAO (power), L9 DDR1_VDD2 (power), M1 DDR1_A6 (out), M2 DDR1_A5 (out), M3 DDR1_A7 (out), M5 DDR1_A3 (out), M6 DDR1_A4 (out), M7 DDR1_ATO, M8 DDR1_VREF (power), M9 DDR1_VDD3 (power), N1 DDR1_A8 (out), N2 DDR1_A10 (out), P1 DDR1_A9 (out), P2 DDR1_A14 (out), P3 DDR1_A13 (out), P4 DDR1_A11 (out), P5 DDR1_ODT0 (out), P6 DDR1_A12 (out), P7 NC4, P8 DDR1_VDDAO (power), P9 DDR1_VDD4 (power), R1 DDR1_A15 (out), R2 DDR1_ODT1 (out), R3 DDR1_DM2 (out), R5 DDR1_DQ19 (io), R6 DDR1_DQ17 (io), R7 NC5, R8 DDR1_DTO1, R9 DDR1_VDD5 (power), T1 DDR1_DQ18 (io), T2 DDR1_DQ16 (io), U1 DDR1_DQS2n (out), U2 DDR1_DQS2 (out), U3 DDR1_DQ22 (io), U4 DDR1_DQ20 (io), U5 DDR1_DM0 (out), U6 DDR1_DQ3 (io), U7 DDR1_PZQ, U8 DDR1_DTO0, V1 DDR1_DQ21 (io), V2 DDR1_DQ23 (io), V3 DDR1_DQ1 (io), V5 DDR1_DQ6 (io), W1 DDR1_DQ4 (io), W2 DDR1_DQ0 (io), Y1 DDR1_DQ2 (io), Y2 DDR1_DQ5 (io), Y3 DDR1_DQ7 (io)
part M pins: A21 VSS9 (power), AC24 VSS11 (power), C3 VSS1 (power), D6 VSS2 (power), D9 VSS3 (power), D12 VSS4 (power), D15 VSS5 (power), D18 VSS6 (power), E20 VSS7 (power), F4 VSS12 (power), J4 VSS13 (power), J9 VSS14 (power), J17 VSS16 (power), J18 VSS28 (power), K10 VSS18 (power), K11 VSS19 (power), K12 VSS20 (power), K13 VSS21 (power), K14 VSS22 (power), K15 VSS23 (power), K16 VSS24 (power), K17 VSS25 (power), K18 VSS26 (power), K19 VSS27 (power), L10 VSS29 (power), L11 VSS30 (power), L13 VSS31 (power), L14 VSS32 (power), L15 VSS33 (power), M4 VSS34 (power), M10 VSS35 (power), M11 VSS36 (power), M13 VSS37 (power), M14 VSS38 (power), N10 VSS40 (power), N11 VSS41 (power), N13 VSS42 (power), N14 VSS43 (power), N15 VSS44 (power), P10 VSS45 (power), P11 VSS46 (power), P13 VSS47 (power), P14 VSS48 (power), P15 VSS49 (power), P16 VSS50 (power), P17 VSS51 (power), P18 VSS52 (power), R4 VSS53 (power), R10 VSS54 (power), R13 VSS55 (power), R14 VSS61 (power), R15 VSS71 (power), R16 VSS56 (power), R17 VSS57 (power), R18 VSS58 (power), R19 VSS59 (power), T10 VSS60 (power), T13 VSS62 (power), T15 VSS64 (power), T16 VSS65 (power), T17 VSS66 (power), T18 VSS67 (power), T19 VSS68 (power), U9 VSS15 (power), U10 VSS70 (power), U13 VSS72 (power), U24 VSS8 (power), V4 VSS73 (power), V9 VSS69 (power), V10 VSS74 (power), V11 VSS75 (power), V12 VSS76 (power), V13 VSS77 (power), W10 VSS17 (power), W11 VSS78 (power), W12 VSS79 (power), W13 VSS80 (power), W14 VSS81 (power), W15 VSS82 (power), W16 VSS83 (power), W17 VSS84 (power), W18 VSS85 (power), W19 VSS86 (power), Y18 VSS39 (power), Y20 VSS63 (power), Y24 VSS10 (power)
part N pins: AA12 eDP_TP_OUT, AA17 eDP_AVDD_1V8 (power), AC17 eDP_CLK24M_IN, AC18 eDP_EXTR, AG14 eDP_TX0P (out), AG15 eDP_TX1P (out), AG16 eDP_TX2P (out), AG17 eDP_TX3P (out), AG18 eDP_AXUP (out), AH14 eDP_TX0N (out), AH15 eDP_TX1N (out), AH16 eDP_TX2N (out), AH17 eDP_TX3N (out), AH18 eDP_AXUN (out), Y17 eDP_AVDD_1V0 (power)
part O pins: AA18 HDMI_AVDD_1V0 (power), AB17 HDMI_EXTR, AB18 HDMI_HPD_d, AB20 HDMI_AVDD_1V8 (power), AD20 AVSS5 (power), AD23 AVSS6 (power), AD26 AVSS7 (power), AF14 AVSS1 (power), AF15 AVSS2 (power), AF17 AVSS3 (power), AF18 AVSS4 (power), AF26 AVSS8 (power), AG19 HDMI_TXCP (out), AG20 HDMI_TX0P (out), AG21 HDMI_TX1P (out), AG22 HDMI_TX2P (out), AH19 HDMI_TXCN (out), AH20 HDMI_TX0N (out), AH21 HDMI_TX1N (out), AH22 HDMI_TX2N (out)
part P pins: AB6 FLASH0_DQS/EMMC_CLKOUT/GPIO3_C2_d (io), AC4 FLASH0_CSn2/EMMC_CMD/GPIO3_C0_u (io), AC5 FLASH0_CSn0/GPIO3_B6_u (io), AD3 FLASH0_D1/EMMC_D1/GPIO3_A1_u (io), AD4 FLASH0_CSn1/GPIO3_B7_u (io), AE3 FLASH0_D0/EMMC_D0/GPIO3_A0_u (io), AF1 FLASH0_D3/EMMC_D3/GPIO3_A3_u (io), AF2 FLASH0_D4/EMMC_D4/GPIO3_A4_u (io), AF3 FLASH0_D2/EMMC_D2/GPIO3_A2_u (io), AF4 FLASH0_ALE/GPIO3_B3_d (io), AG1 FLASH0_D6/EMMC_D6/GPIO3_A6_u (io), AG2 FLASH0_D7/EMMC_D7/GPIO3_A7_u (io), AG3 FLASH0_D5/EMMC_D5/GPIO3_A5_u (io), AG4 FLASH0_WRN/GPIO3_B5_u (io), AH1 FLASH0_WP/EMMC_PWREN/GPIO3_B1_d (io), AH2 FLASH0_RDY/GPIO3_B0_u (io), AH3 FLASH0_CLE/GPIO3_B4_d (io), Y6 FLASH0_RDN/GPIO3_B2_u (io), Y7 FLASH0_CSn3/EMMC_RSTNOUT/GPIO3_C1_u (io), Y8 FLASH0_VOLTAGE_SEL/GPIO3_C3_d (io), Y9 FLASH0_VDD (power)
part Q pins: AA3 HOST_D6/MAC_RXD0/SDIO1_BKPWR/FLASH1_D6/GPIO3_D6_u (io), AA4 HOST_D7/MAC_RXD1/SDIO1_INTn/FLASH1_D7/GPIO3_D7_u (io), AA5 HOST_D14/MAC_COL/FLASH1_DQS/FLASH1_CSn3/GPIO4_B0_u (io), AA6 HOST_D13/MAC_CRS/SDIO1_CLKOUT/FLASH1_CSn1/GPIO4_A7_u (io), AB1 HOST_D2/MAC_RXD2/SDIO1_D2/FLASH1_D2/GPIO3_D2_u (io), AB2 HOST_D5/MAC_TXD1/SDIO1_WRPRT/FLASH1_D5/GPIO3_D5_u (io), AB5 HOST_D12/MAC_RXCLK/SDIO1_CMD/FLASH1_CSn0/GPIO4_A6_u (io), AC1 HOST_D3/MAC_RXD3/SDIO1_D3/FLASH1_D3/GPIO3_D3_u (io), AC2 HOST_CKOUTN/MAC_RXDV/FLASH0_CSn4/FLASH1_WP/GPIO4_A1_u (io), AC3 HOST_CKOUTP/MAC_MDC/FLASH1_RDY/GPIO4_A0_u (io), AD1 HOST_D4/MAC_TXD0/SDIO1_DET/FLASH1_D4/GPIO3_D4_u (io), AD2 HOST_D10/MAC_TXEN/FLASH0_CSn7/FLASH1_CLE/GPIO4_A4_u (io), AE1 HOST_D8/MAC_RXER/FLASH0_CSn5/FLASH1_RDN/GPIO4_A2_u (io), AE2 HOST_D9/MAC_CLK/FLASH0_CSn6/FLASH1_ALE/GPIO4_A3_u (io), V6 HOST_D1/MAC_TXD3/SDIO1_D1/FLASH1_D1/GPIO3_D1_u (io), V7 HOST_D15/MAC_TXCLK/SDIO1_PWREN/FLASH1_CSn2/GPIO4_B1_u (io), V8 FLASH1_VDD (power), Y4 HOST_D0/MAC_TXD2/SDIO1_D0/FLASH1_D0/GPIO3_D0_u (io), Y5 HOST_D11/MAC_MDIO/FLASH1_WRN/GPIO4_A5_u (io)
part R pins: L12 LOGIC_VDD1 (power), L16 GPU_VDD1 (power), L17 GPU_VDD2 (power), L18 GPU_VDD3 (power), L19 GPU_VDD4 (power), M12 LOGIC_VDD2 (power), M15 GPU_VDD_COM, M16 GPU_VDD5 (power), M17 GPU_VDD6 (power), M18 GPU_VDD7 (power), M19 GPU_VDD8 (power), N12 LOGIC_VDD3 (power), N16 GPU_VDD9 (power), N17 GPU_VDD10 (power), N18 GPU_VDD11 (power), N19 GPU_VDD12 (power), P12 LOGIC_VDD4 (power), R11 LOGIC_VDD8 (power), R12 LOGIC_VDD5 (power), T11 LOGIC_VDD9 (power), T12 LOGIC_VDD6 (power), T14 CPU_VDD_COM, U11 LOGIC_VDD10 (power), U12 LOGIC_VDD7 (power), U14 CPU_VDD1 (power), U15 CPU_VDD2 (power), U16 CPU_VDD3 (power), U17 CPU_VDD4 (power), U18 CPU_VDD5 (power), U19 CPU_VDD6 (power), V14 CPU_VDD7 (power), V15 CPU_VDD8 (power), V16 CPU_VDD9 (power), V17 CPU_VDD10 (power), V18 CPU_VDD11 (power), V19 CPU_VDD12 (power), V20 LCDC_VDD (power)
part S pins: A24 NC11 (in), A25 NC9 (out), AA14 NC28 (power), AA15 NC18 (power), AB14 NC14 (out), AB15 NC13 (out), AC14 NC16 (in), AC15 NC15 (in), AD14 NC20 (in), AD15 NC24 (out), AD17 NC22 (in), AD18 NC26 (out), AE14 NC19 (in), AE15 NC23 (out), AE17 NC21 (in), AE18 NC25 (out), B24 NC12 (in), B25 NC10 (out), G9 NC7, J7 NC8, Y14 NC27 (power), Y15 NC17 (power)
part T pins: P21 RECOVER/ADC_IN1 (in), P23 ADC_IN2 (in), P24 ADC_IN0 (in), R20 ADC_AVDD_1V8 (power)
part U pins: A27 HSIC_DATA, B27 HSIC_STROBE, H20 HSIC_AVDD_1V2 (power)
part V pins: AC22 MIPI_TX_AVDD_1V8 (power), AC27 MIPI_TX_D3P (out), AC28 MIPI_TX_D3N (out), AD27 MIPI_TX_D2P (out), AD28 MIPI_TX_D2N (out), AE26 MIPI_TX_REXT, AE27 MIPI_TX_CLKP (out), AE28 MIPI_TX_CLKN (out), AF27 MIPI_TX_D1P (out), AF28 MIPI_TX_D1N (out), AG27 MIPI_TX_D0P (out), AG28 MIPI_TX_D0N (out)
part W pins: AC20 MIPI_RX_AVDD_1V8 (power), AD21 MIPI_RX_REXT, AG23 MIPI_RX_D0P (in), AG24 MIPI_RX_D1P (in), AG25 MIPI_RX_CLKP (in), AG26 MIPI_RX_D2P (in), AH23 MIPI_RX_D0N (in), AH24 MIPI_RX_D1N (in), AH25 MIPI_RX_CLKN (in), AH26 MIPI_RX_D2N (in), AH27 MIPI_RX_D3N (in), AH28 MIPI_RX_D3P (in)
part X pins: AC21 MIPI_TX/RX_AVDD_1V8 (power), AD22 MIPI_TX/RX_REXT, AD25 MIPI_TX/RX_D3N (io), AE20 MIPI_TX/RX_D0P (io), AE21 MIPI_TX/RX_D1P (io), AE23 MIPI_TX/RX_CLKP (io), AE24 MIPI_TX/RX_D2P (io), AF20 MIPI_TX/RX_D0N (io), AF21 MIPI_TX/RX_D1N (io), AF23 MIPI_TX/RX_CLKN (io), AF24 MIPI_TX/RX_D2N (io), AF25 MIPI_TX/RX_D3P (io)

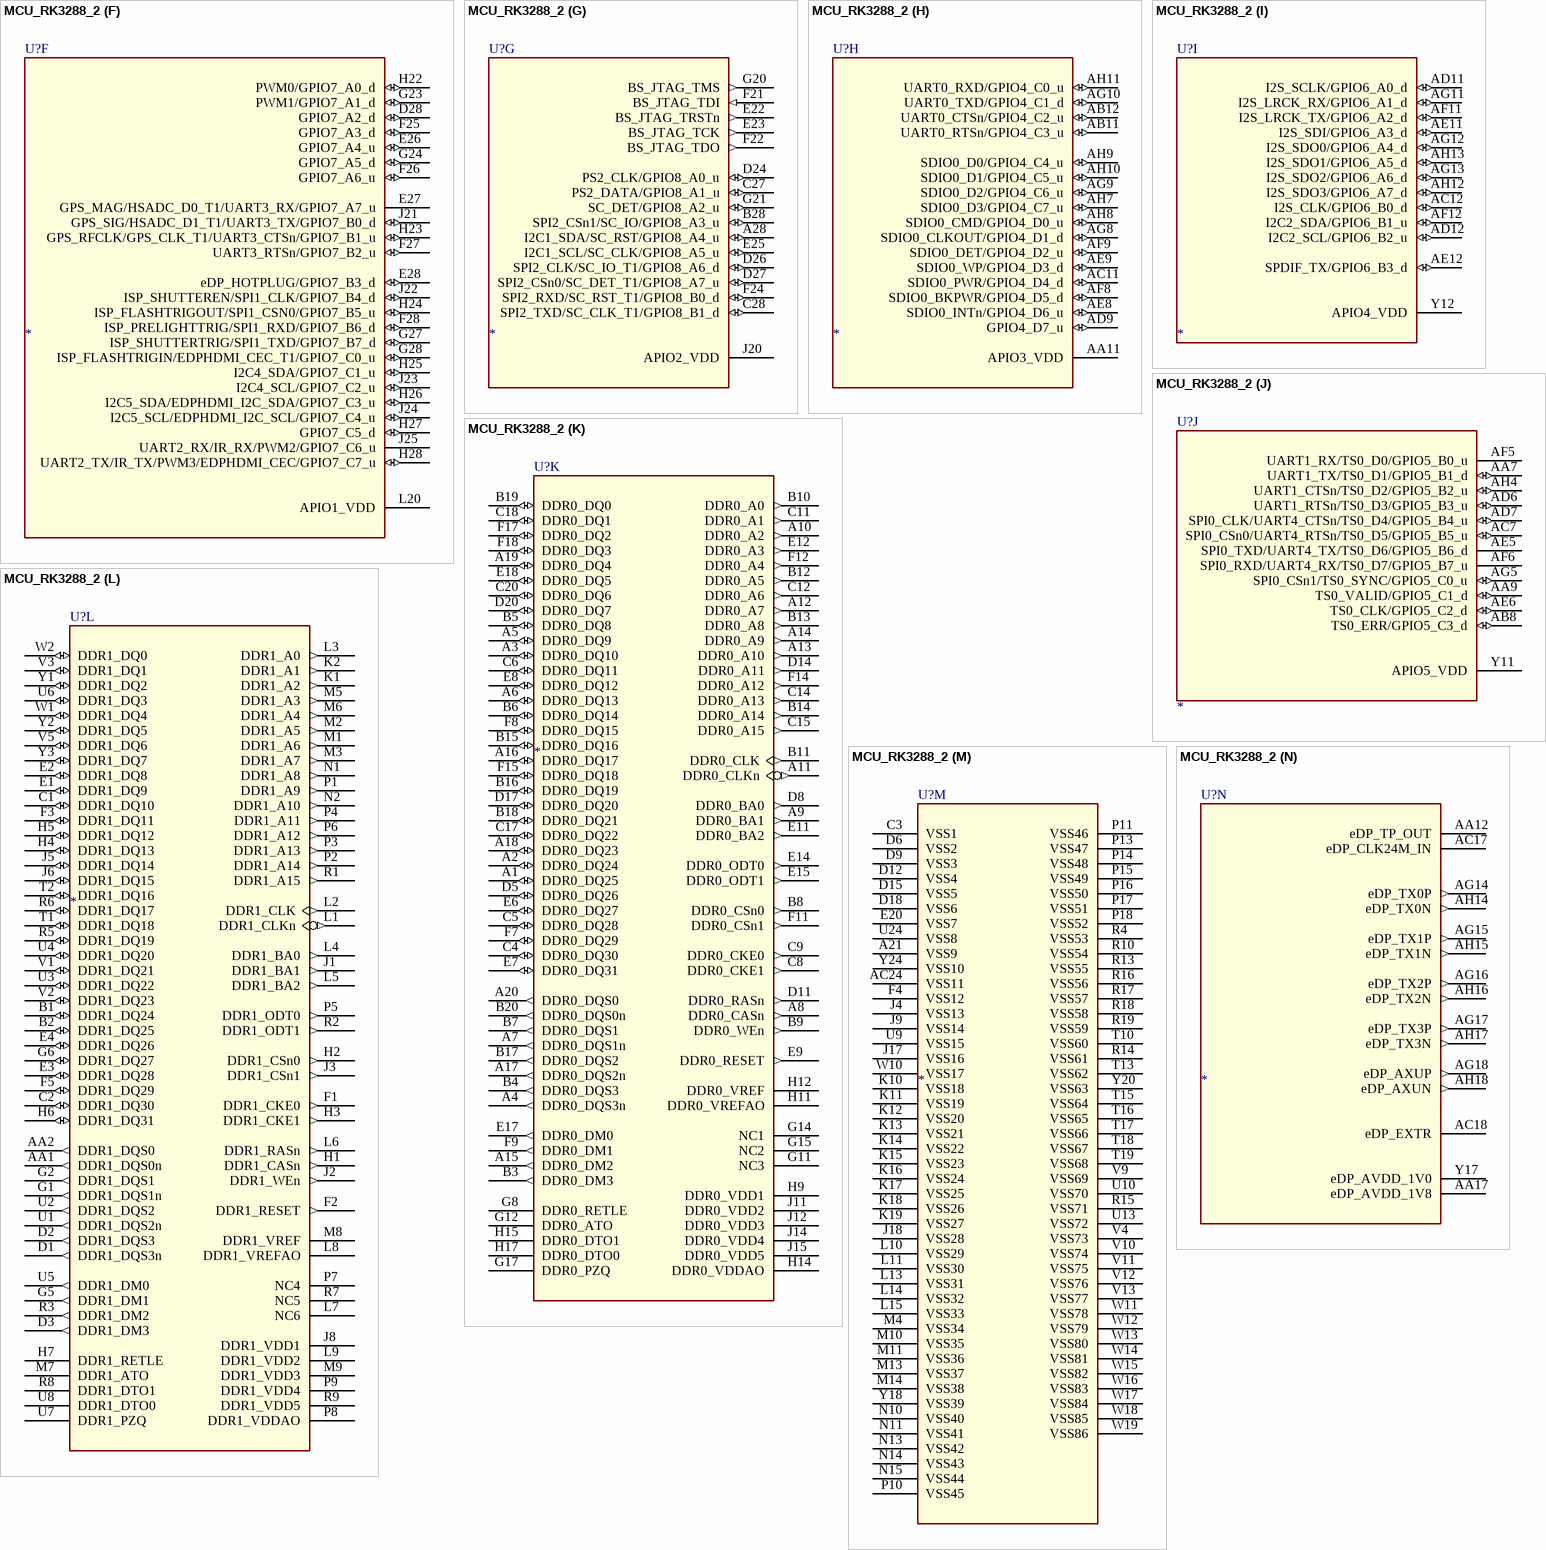
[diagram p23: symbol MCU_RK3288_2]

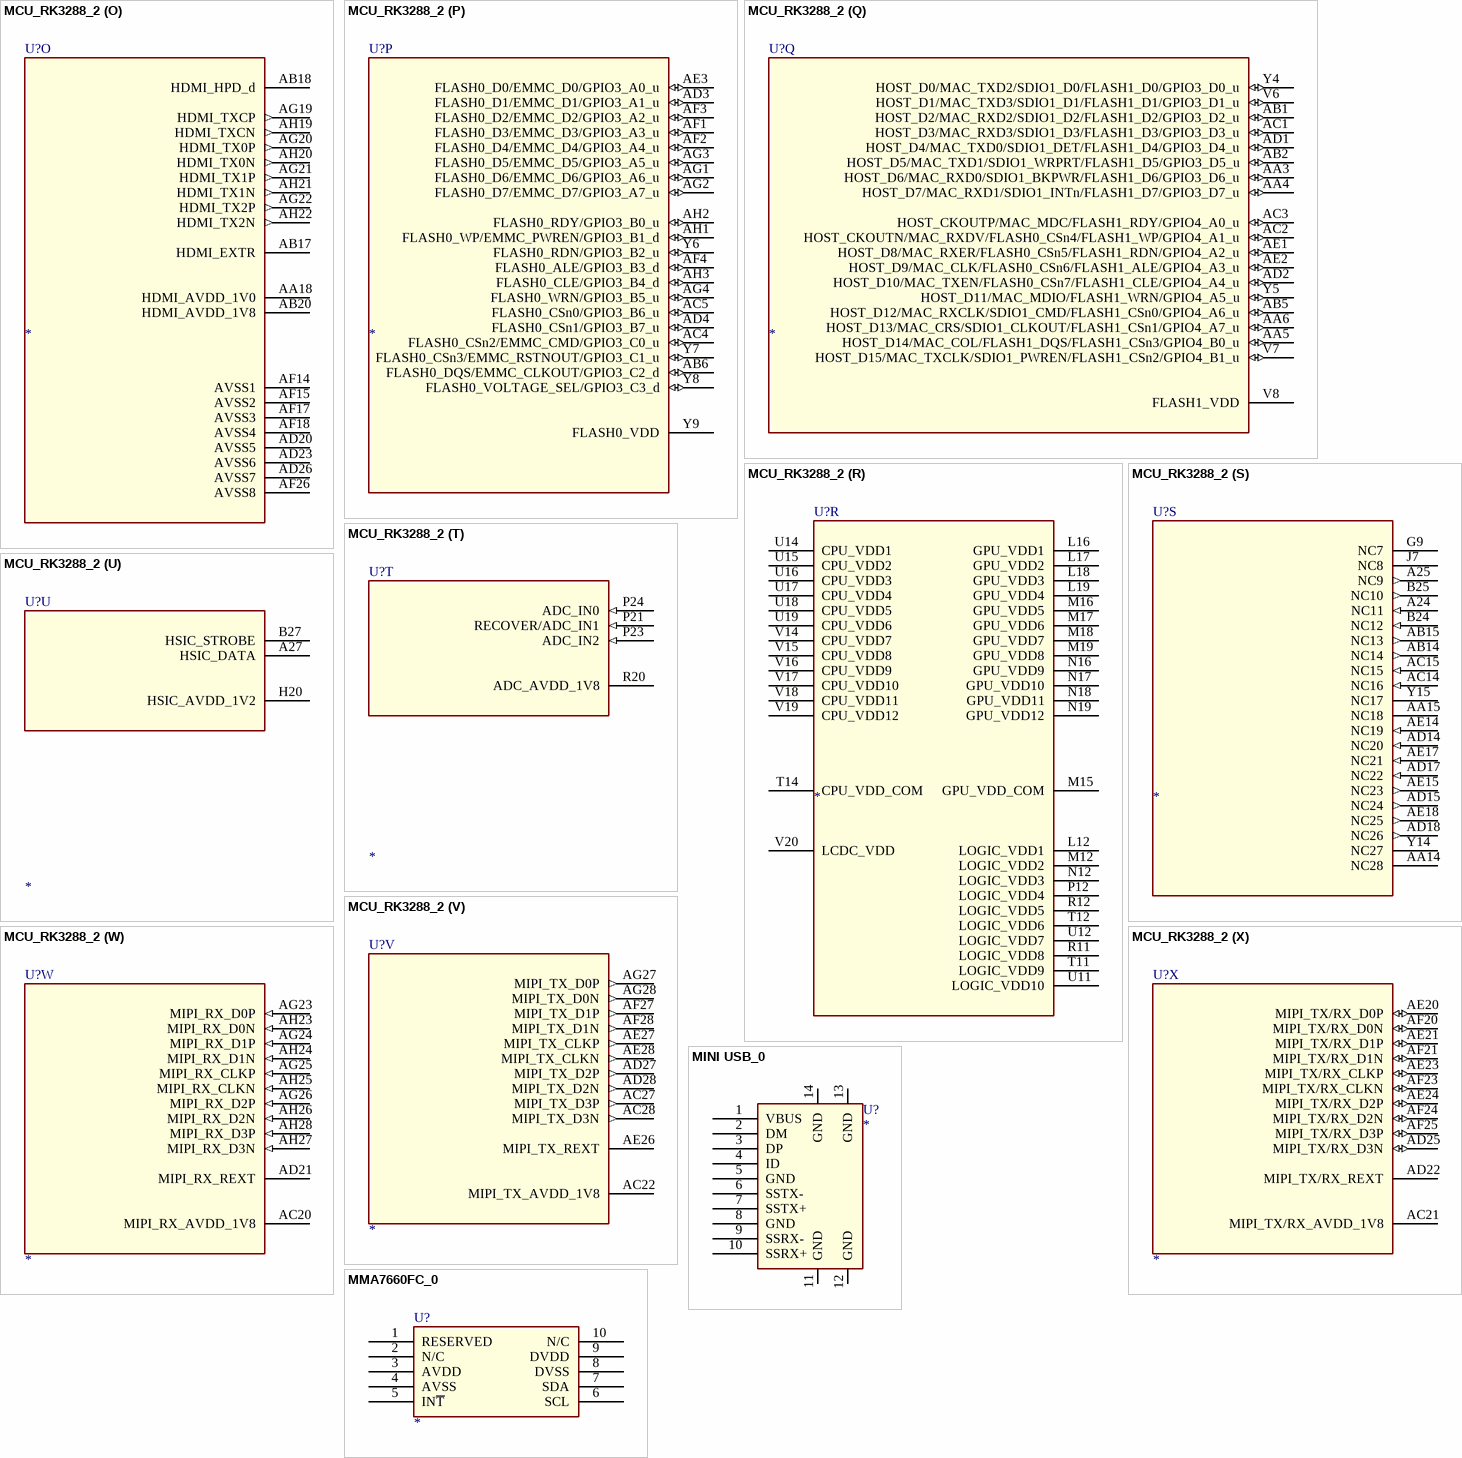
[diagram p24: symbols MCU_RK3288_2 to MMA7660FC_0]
